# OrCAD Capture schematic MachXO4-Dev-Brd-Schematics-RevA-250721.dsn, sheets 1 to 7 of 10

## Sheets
1 Title page: title: LFMXO4-110-EVN; rev: 1.0; note: 305-PD-25-0689
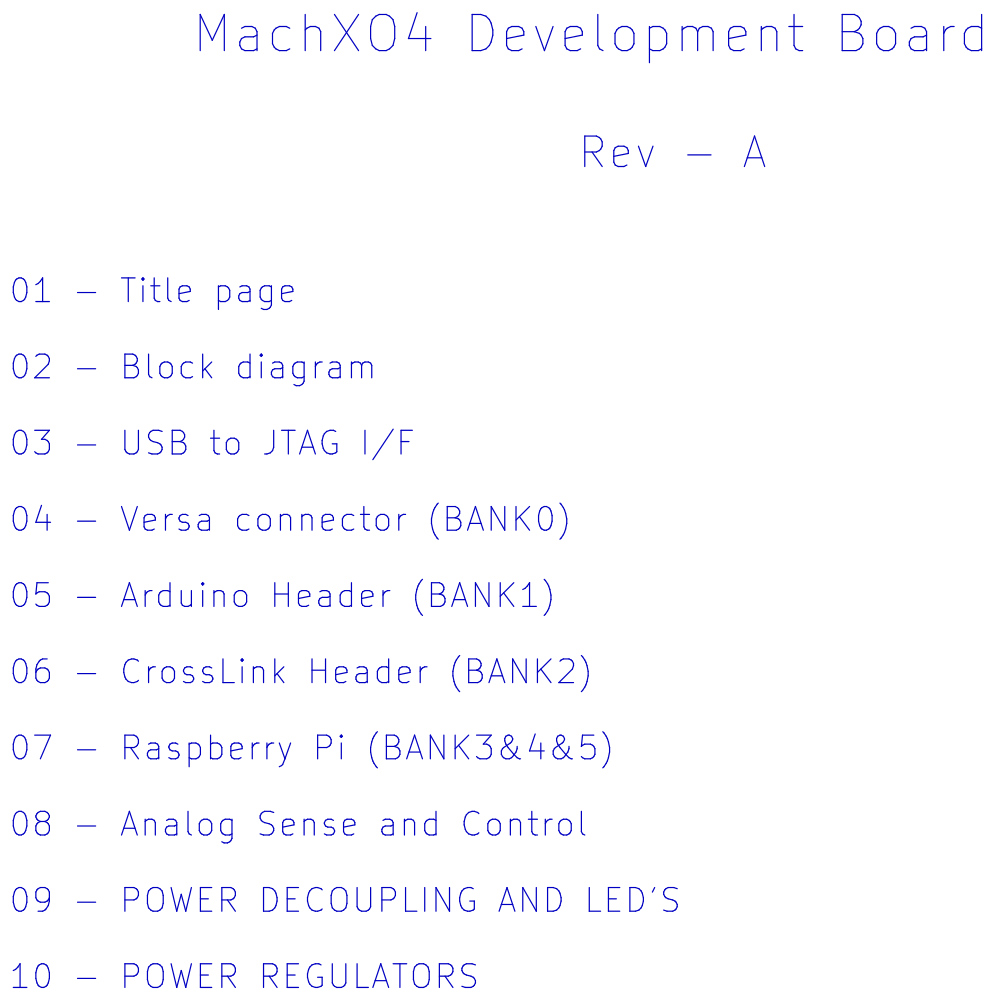
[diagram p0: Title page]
2 Block diagram
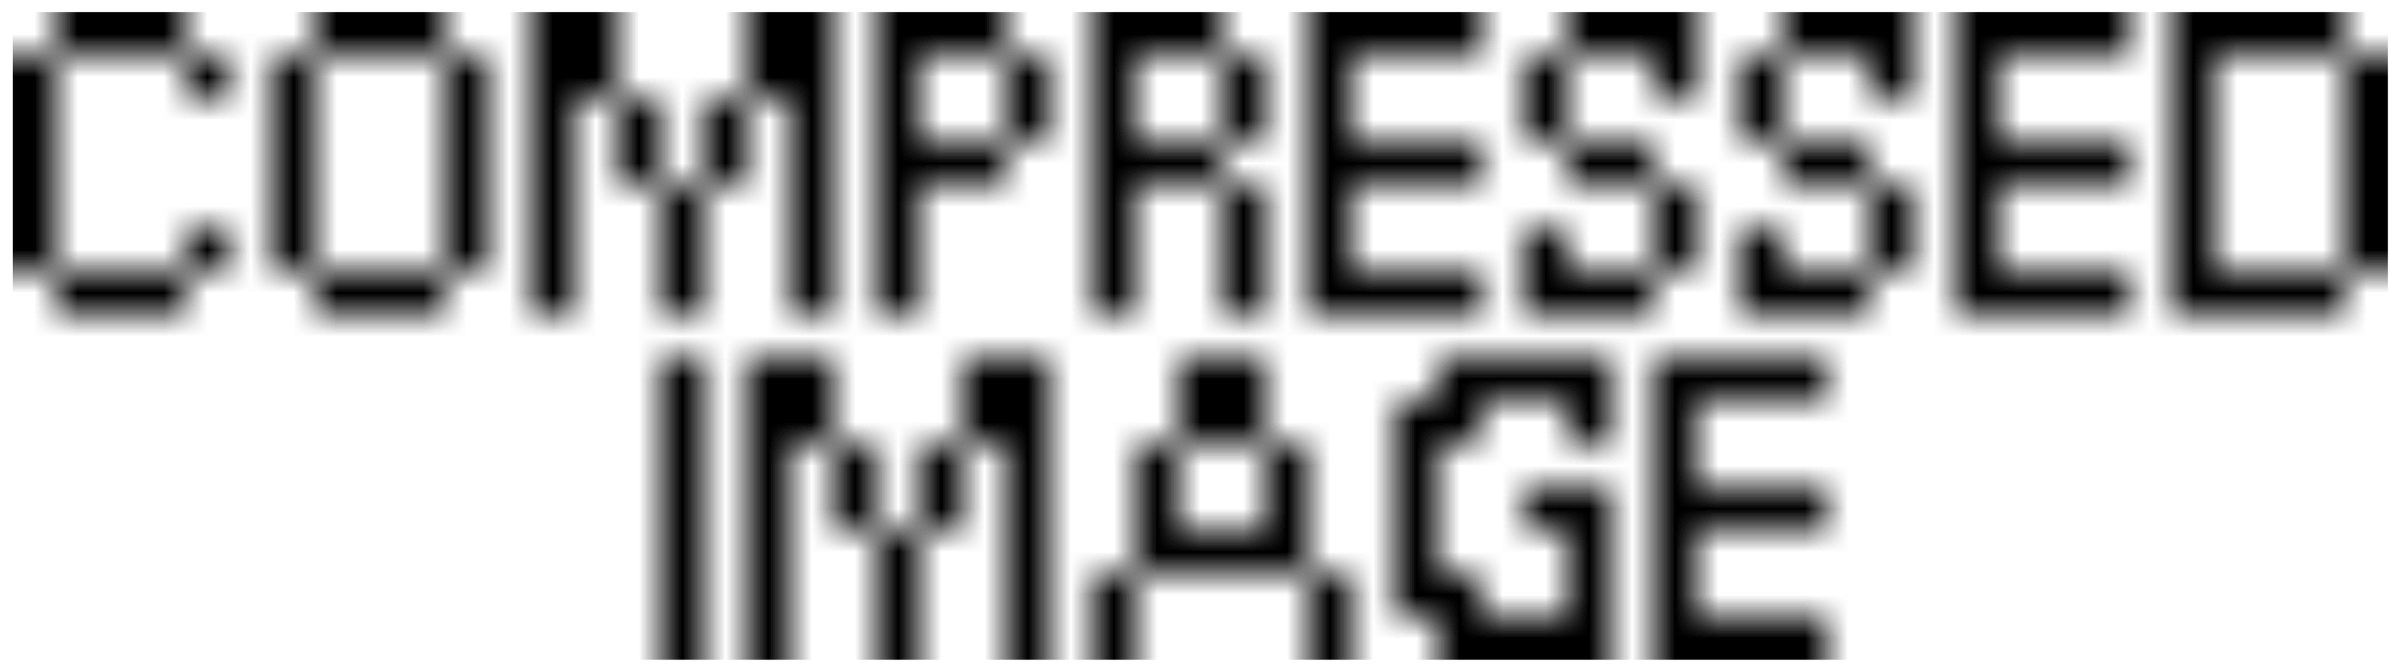
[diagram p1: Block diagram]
3 USB to JTAG I/F: size B
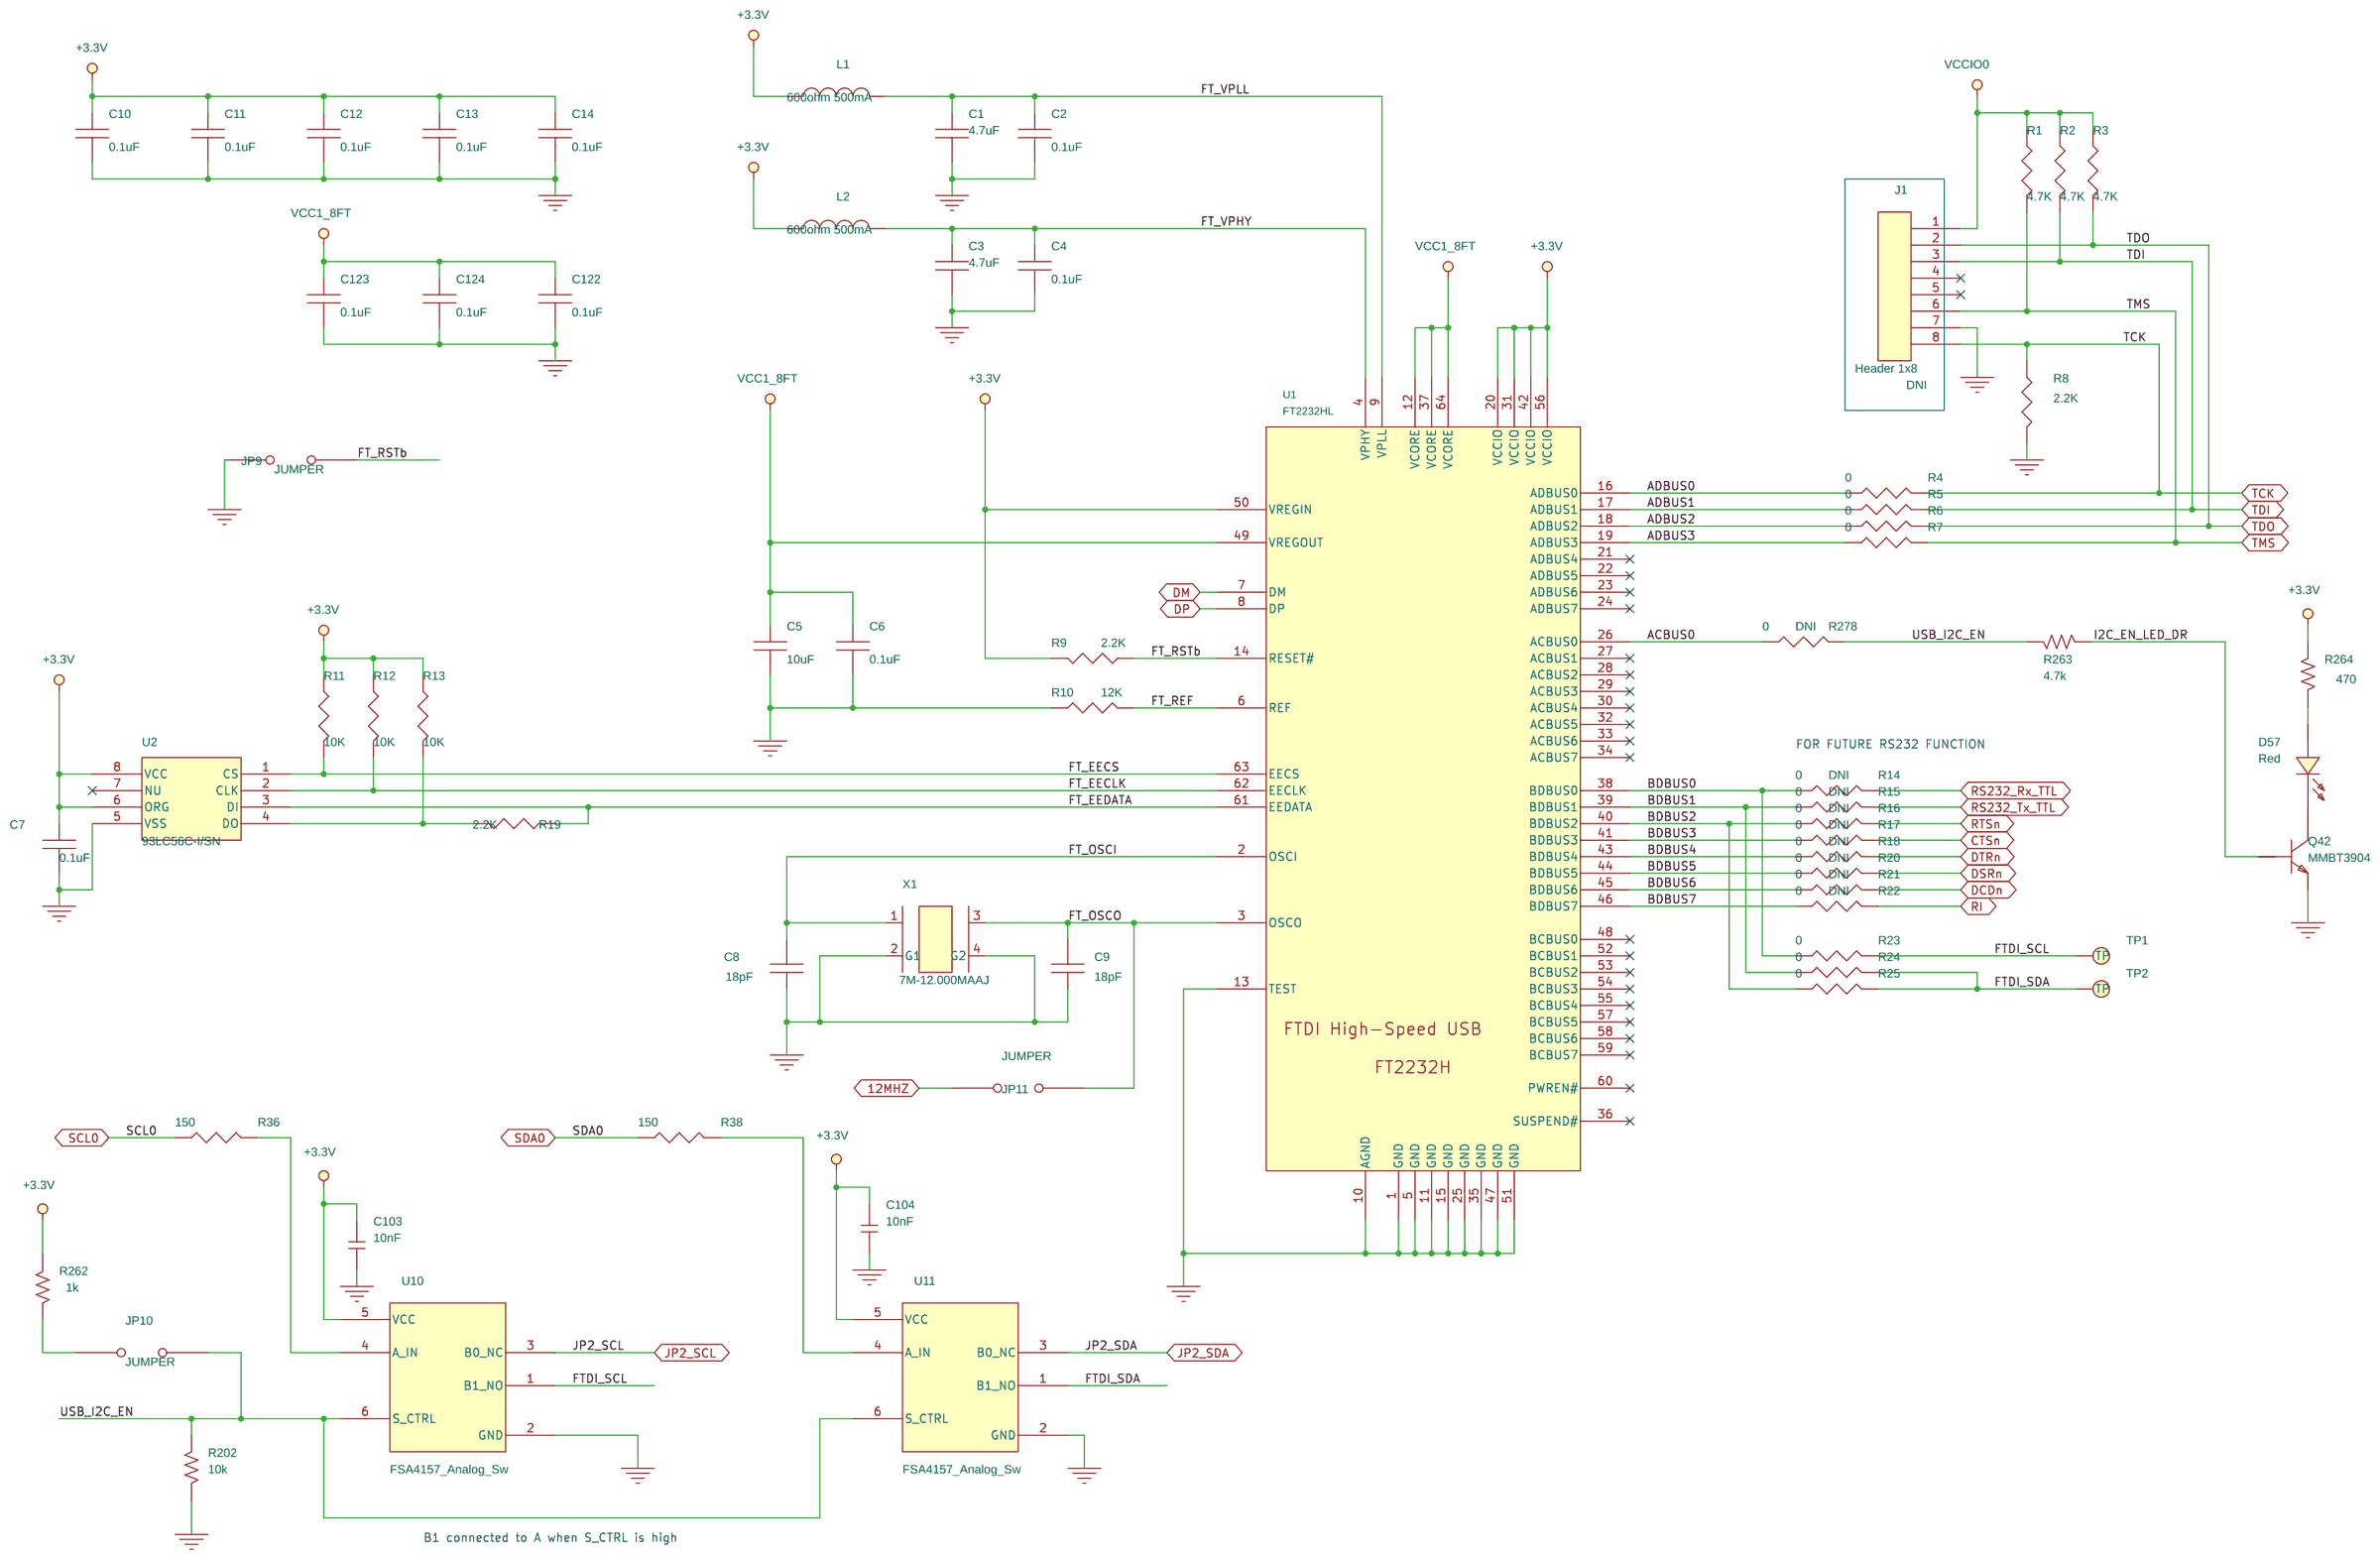
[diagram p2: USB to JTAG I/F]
4 Versa connector (BANK0): size B
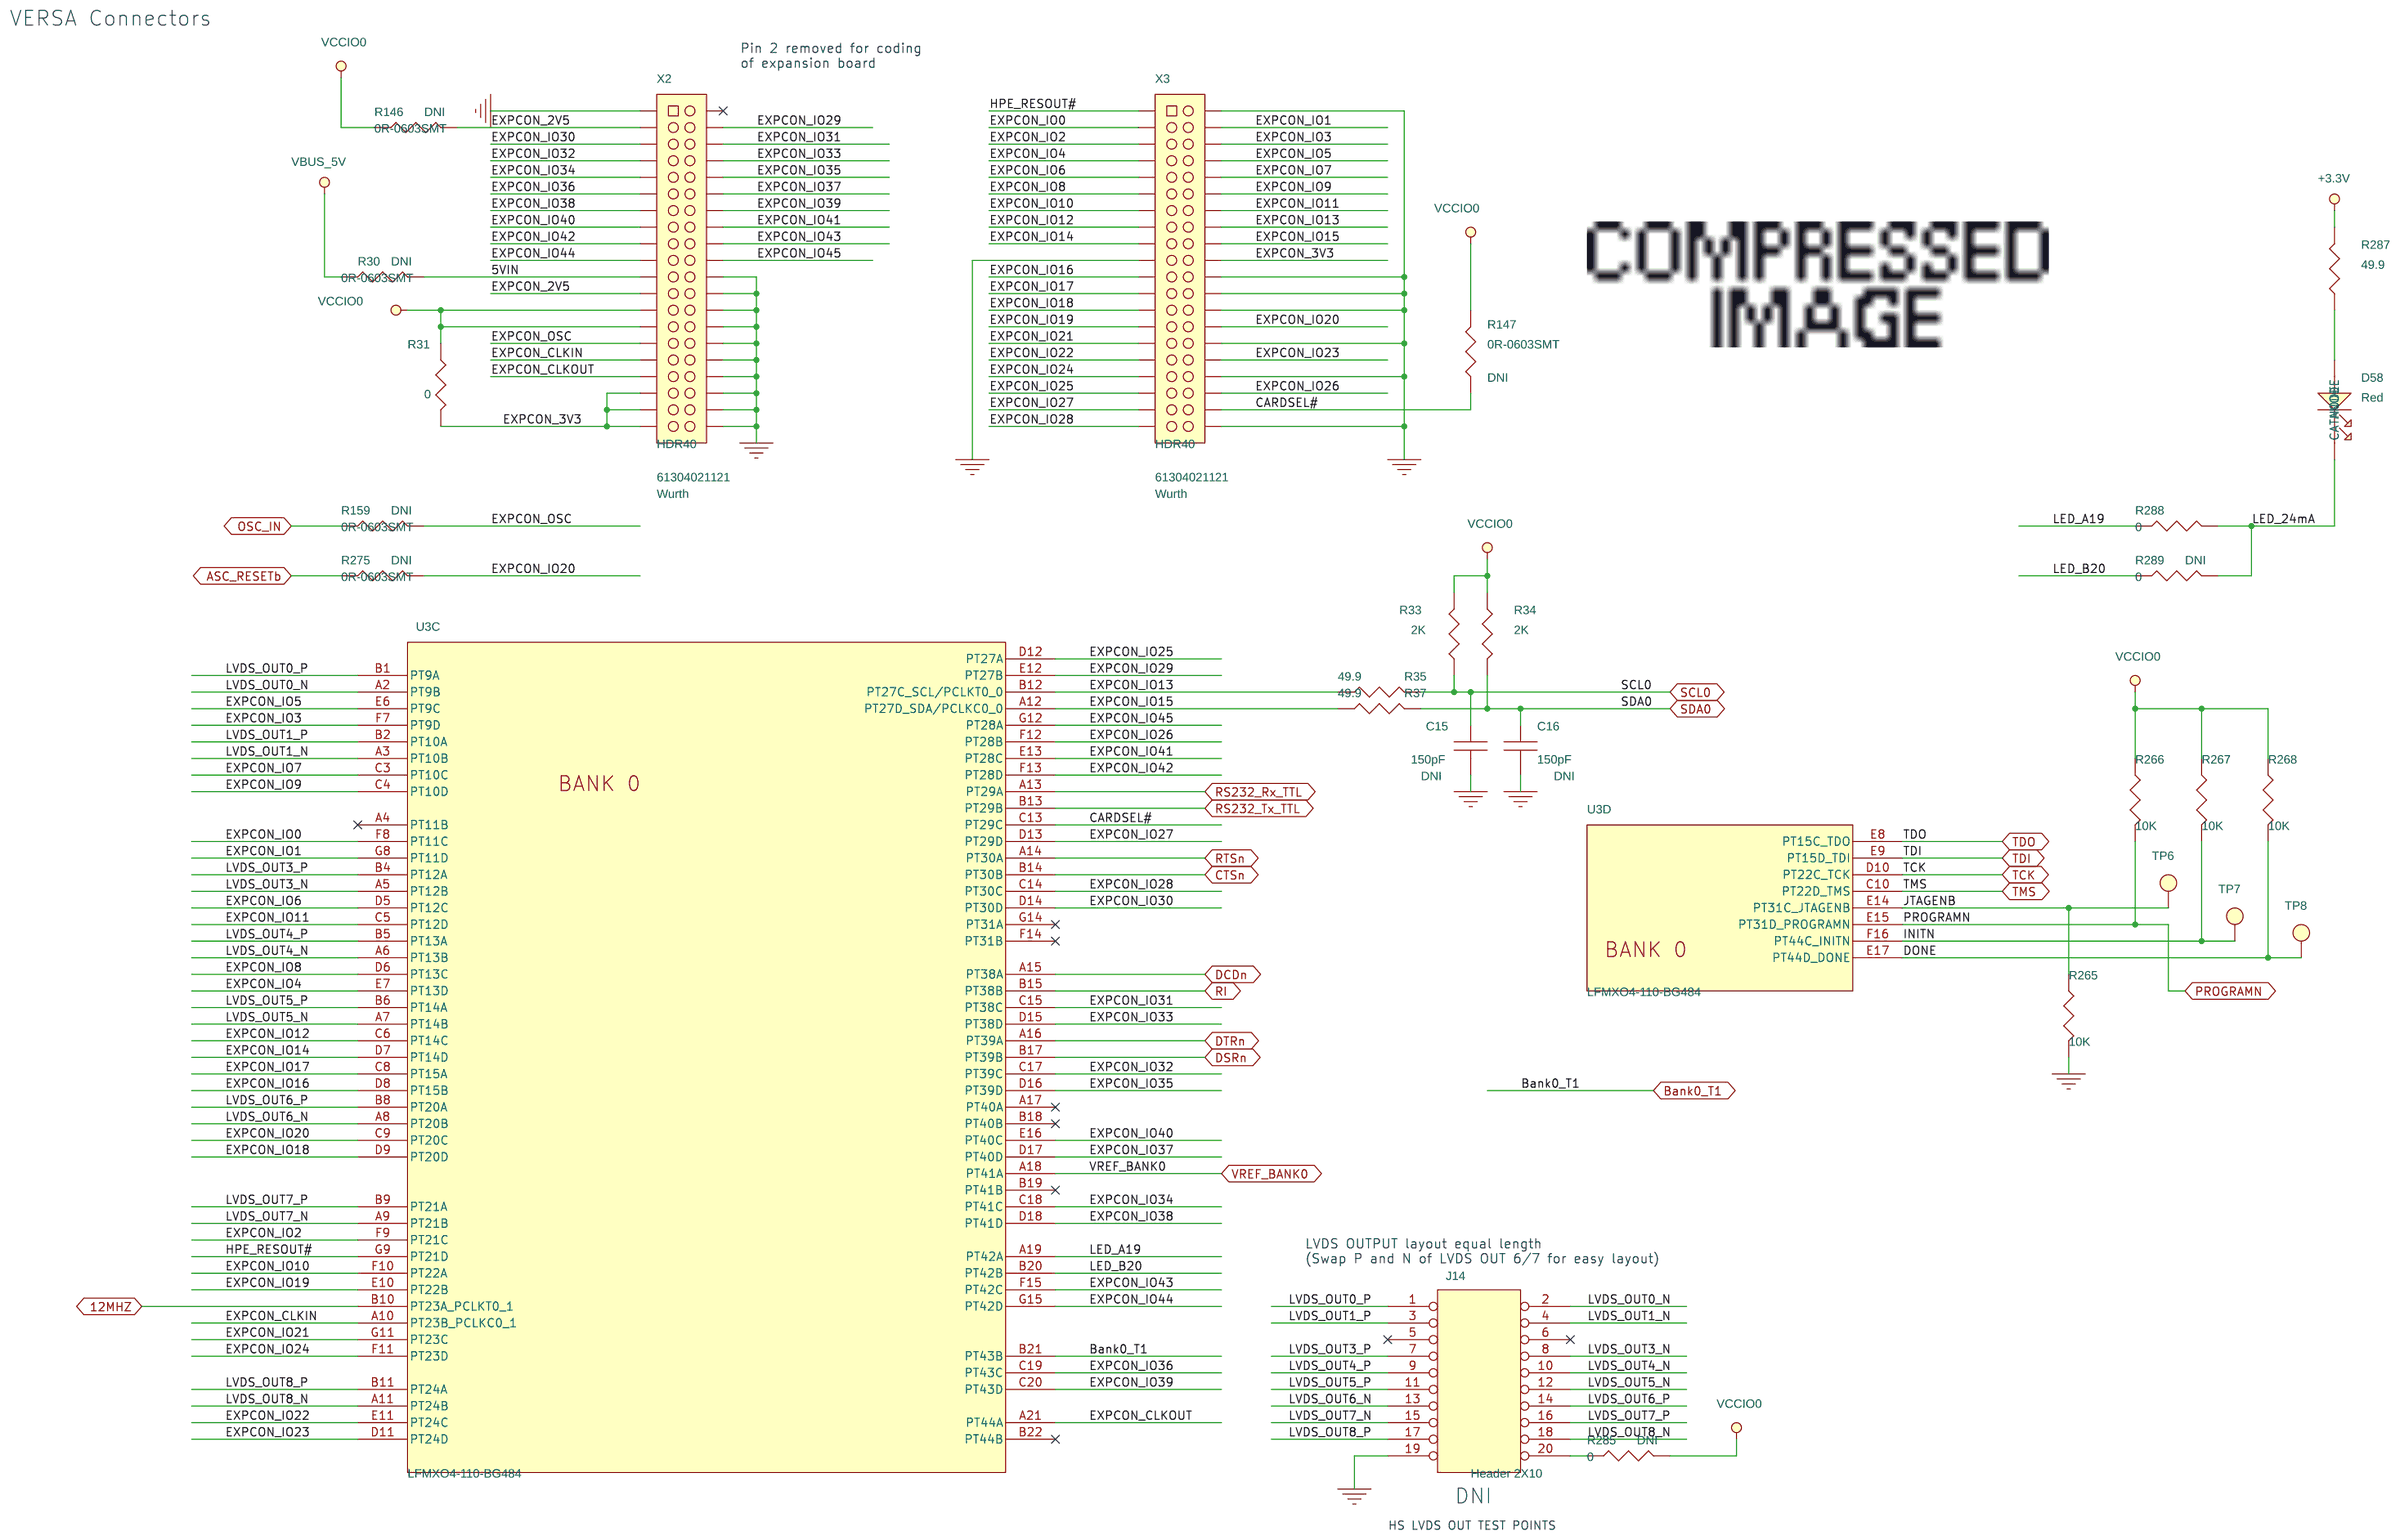
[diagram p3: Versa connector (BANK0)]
5 Arduino Header (BANK1): size B
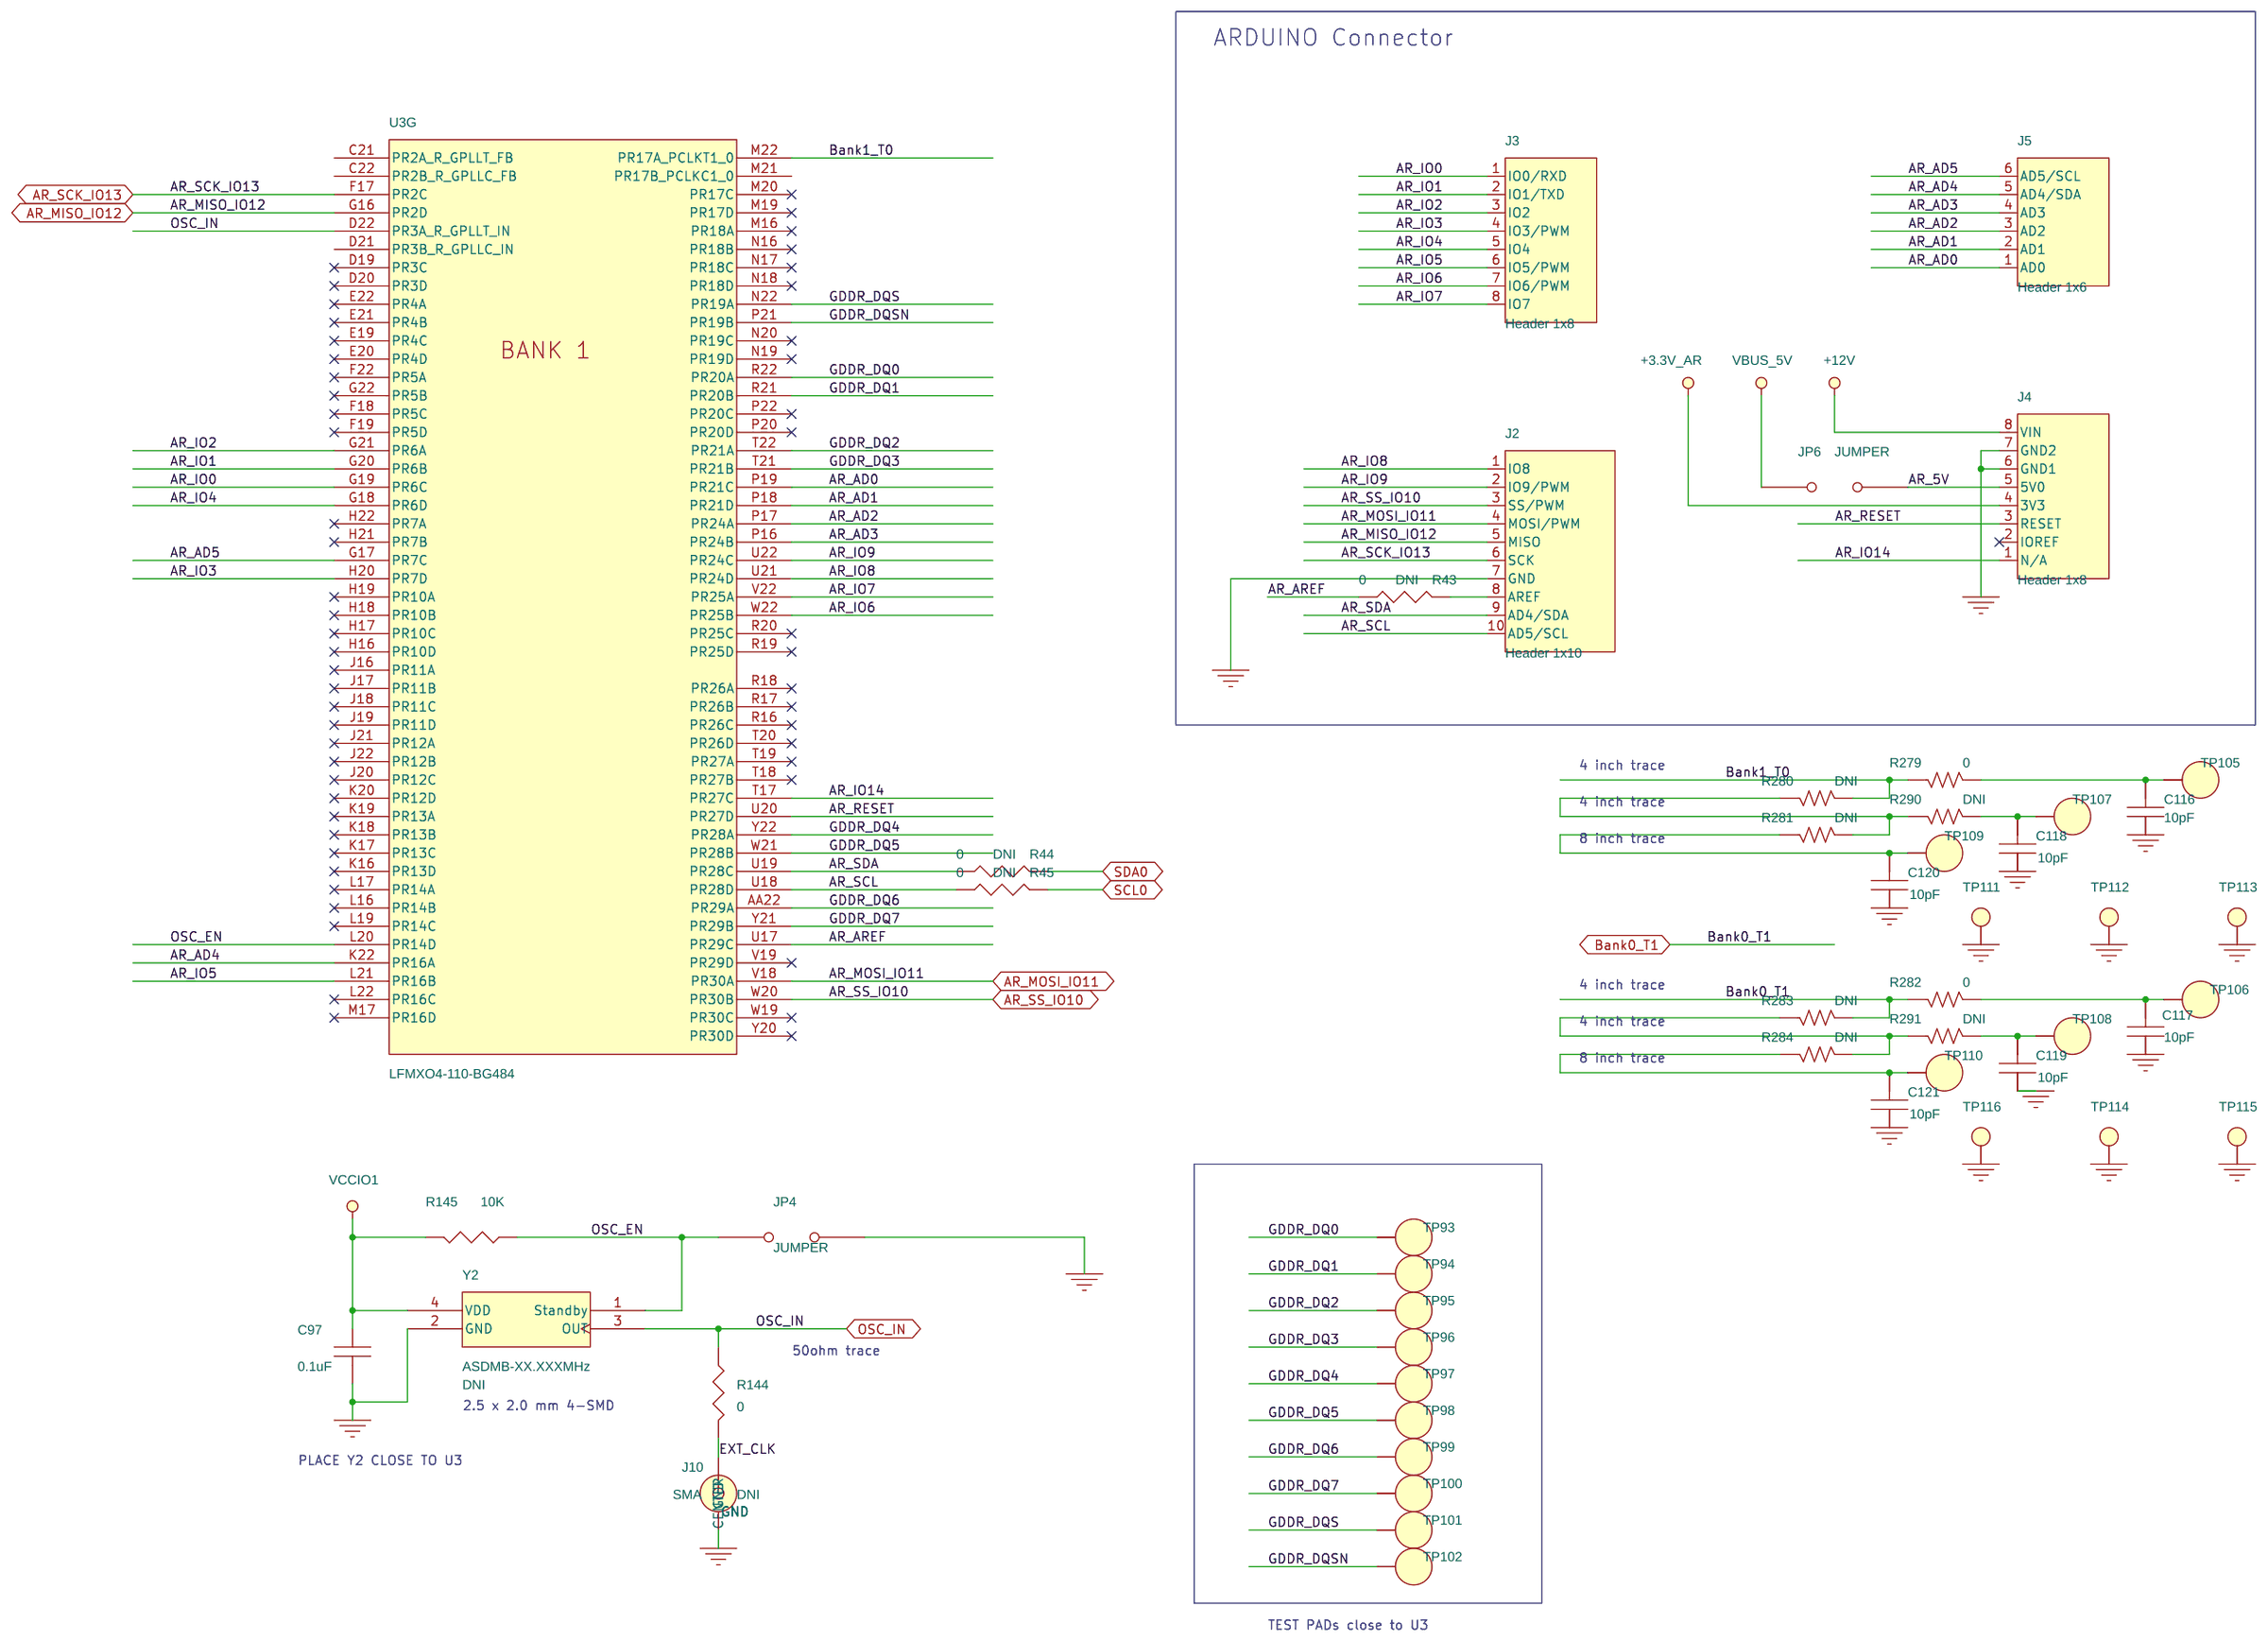
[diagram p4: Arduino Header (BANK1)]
6 CrossLink Header (BANK2): size C
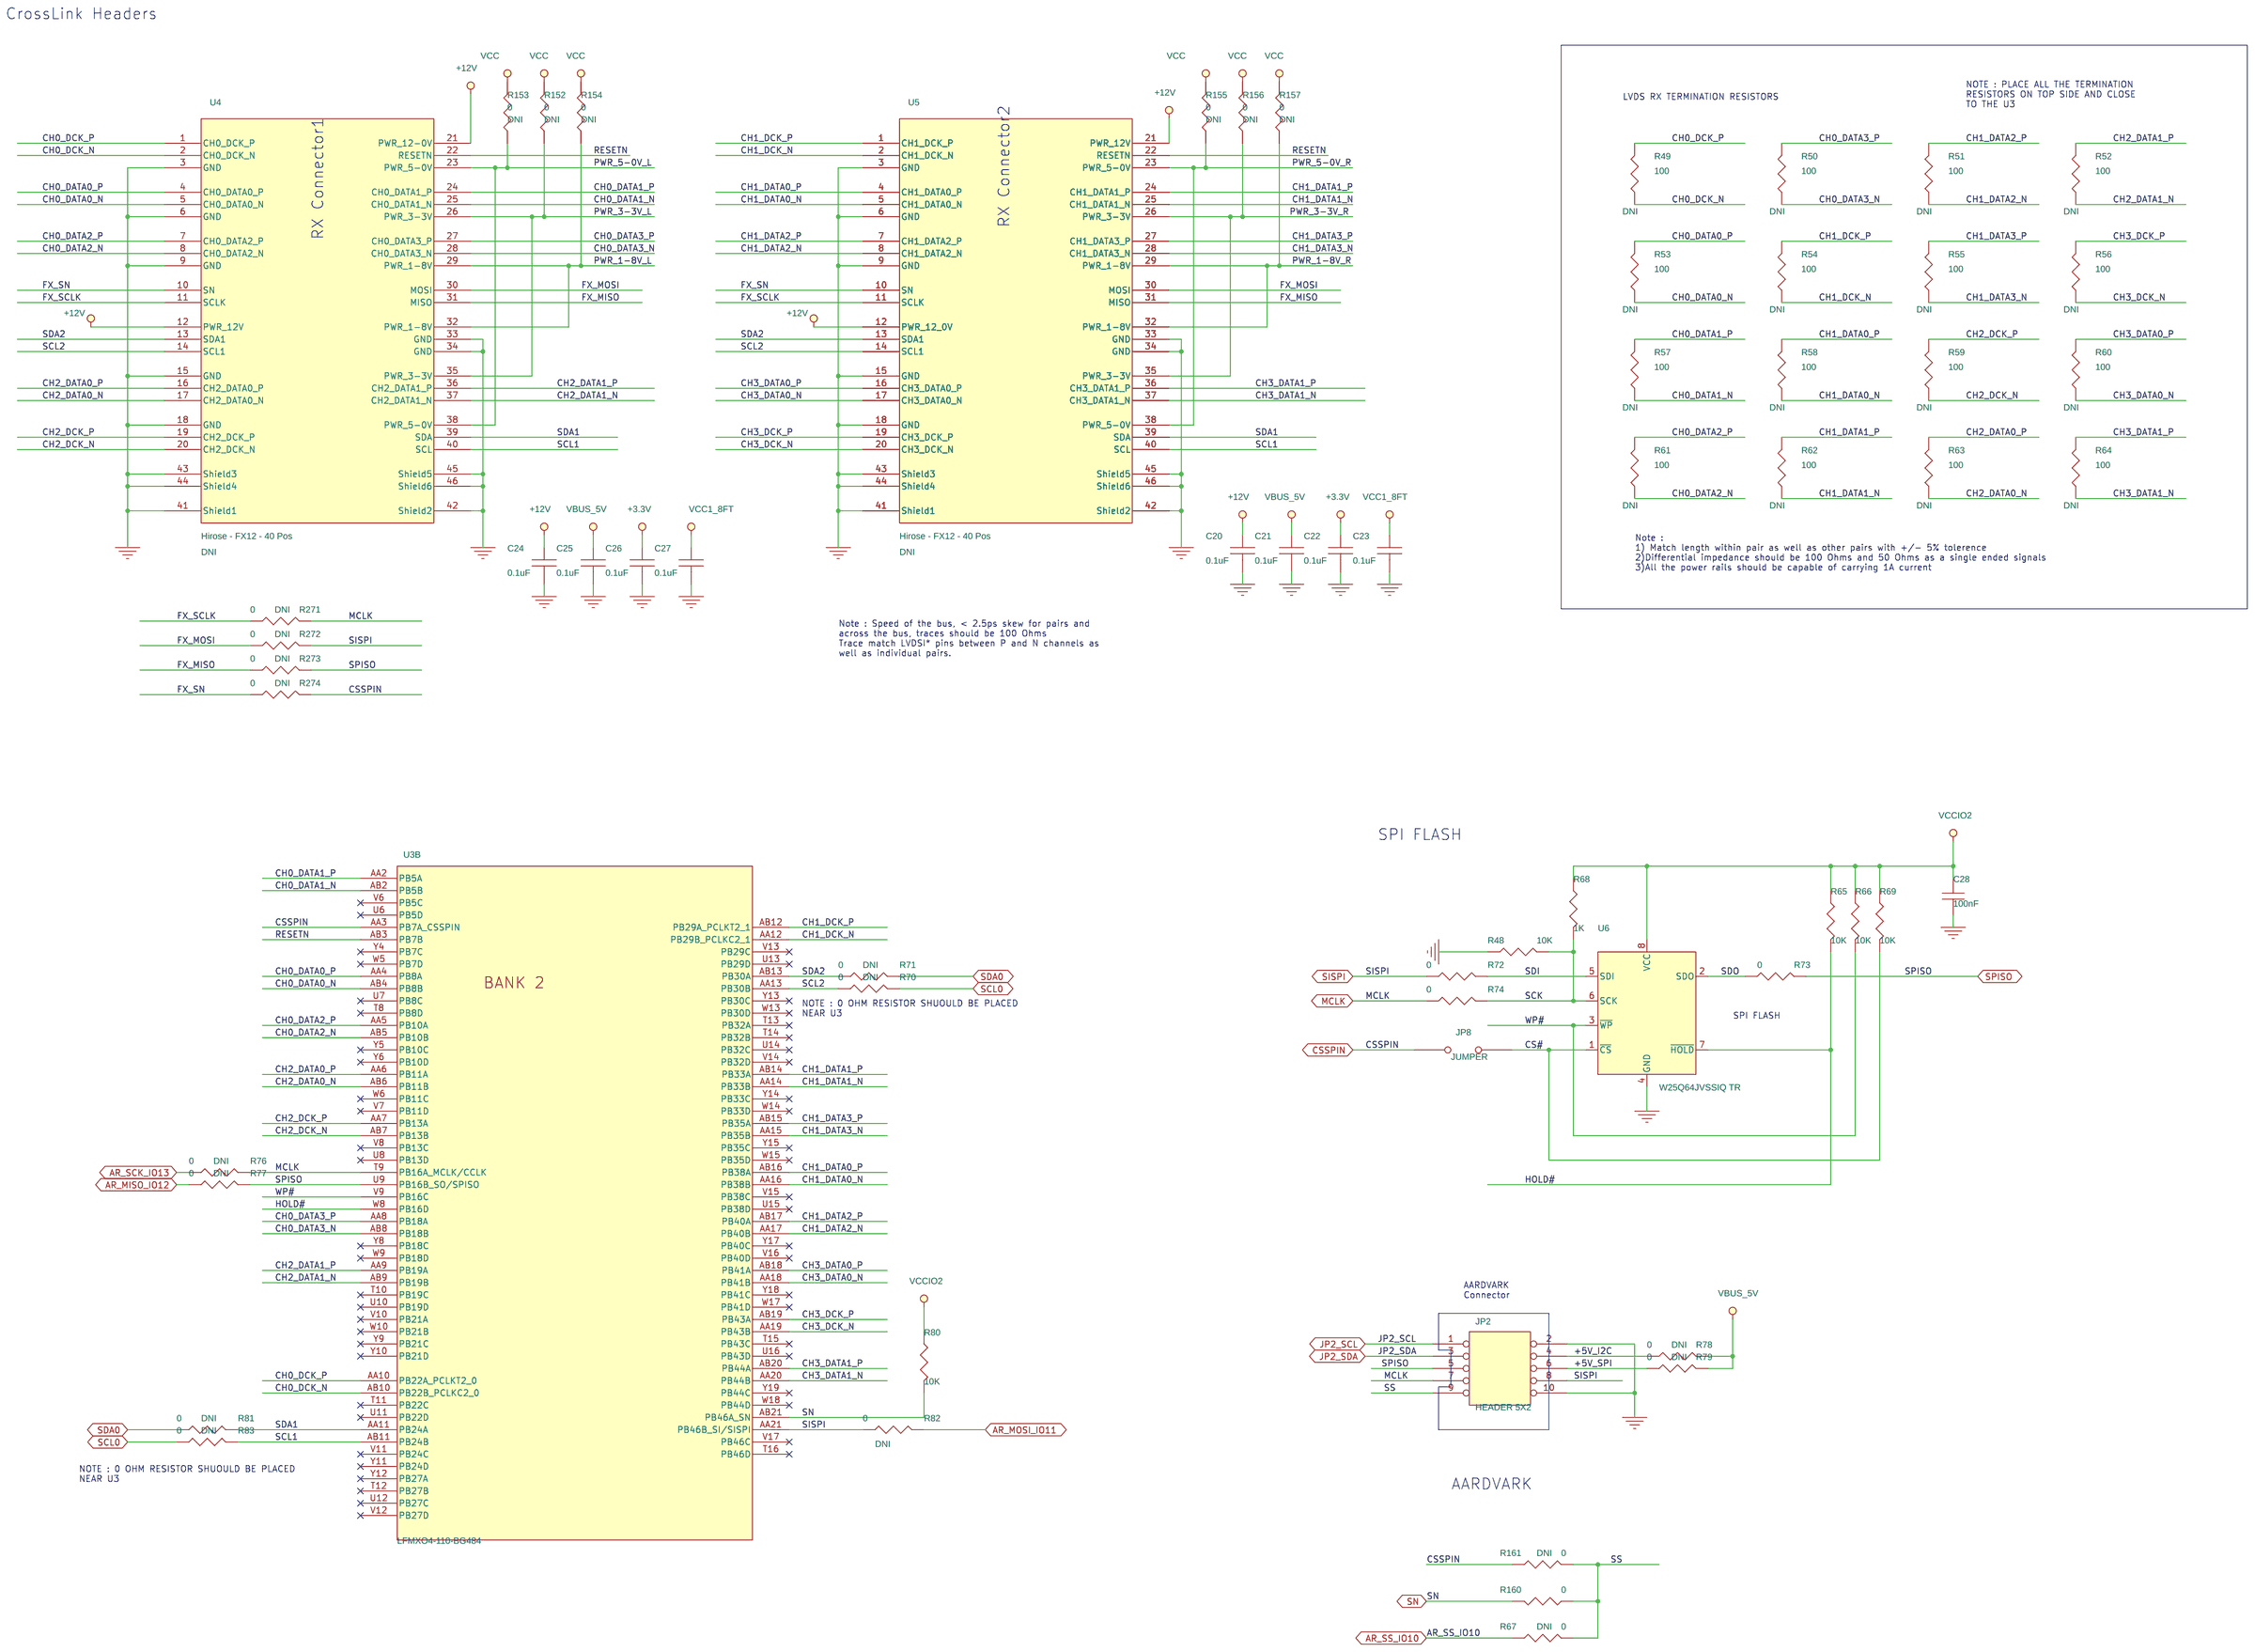
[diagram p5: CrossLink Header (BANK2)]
7 Raspberry Pi (BANK3&4&5): size B
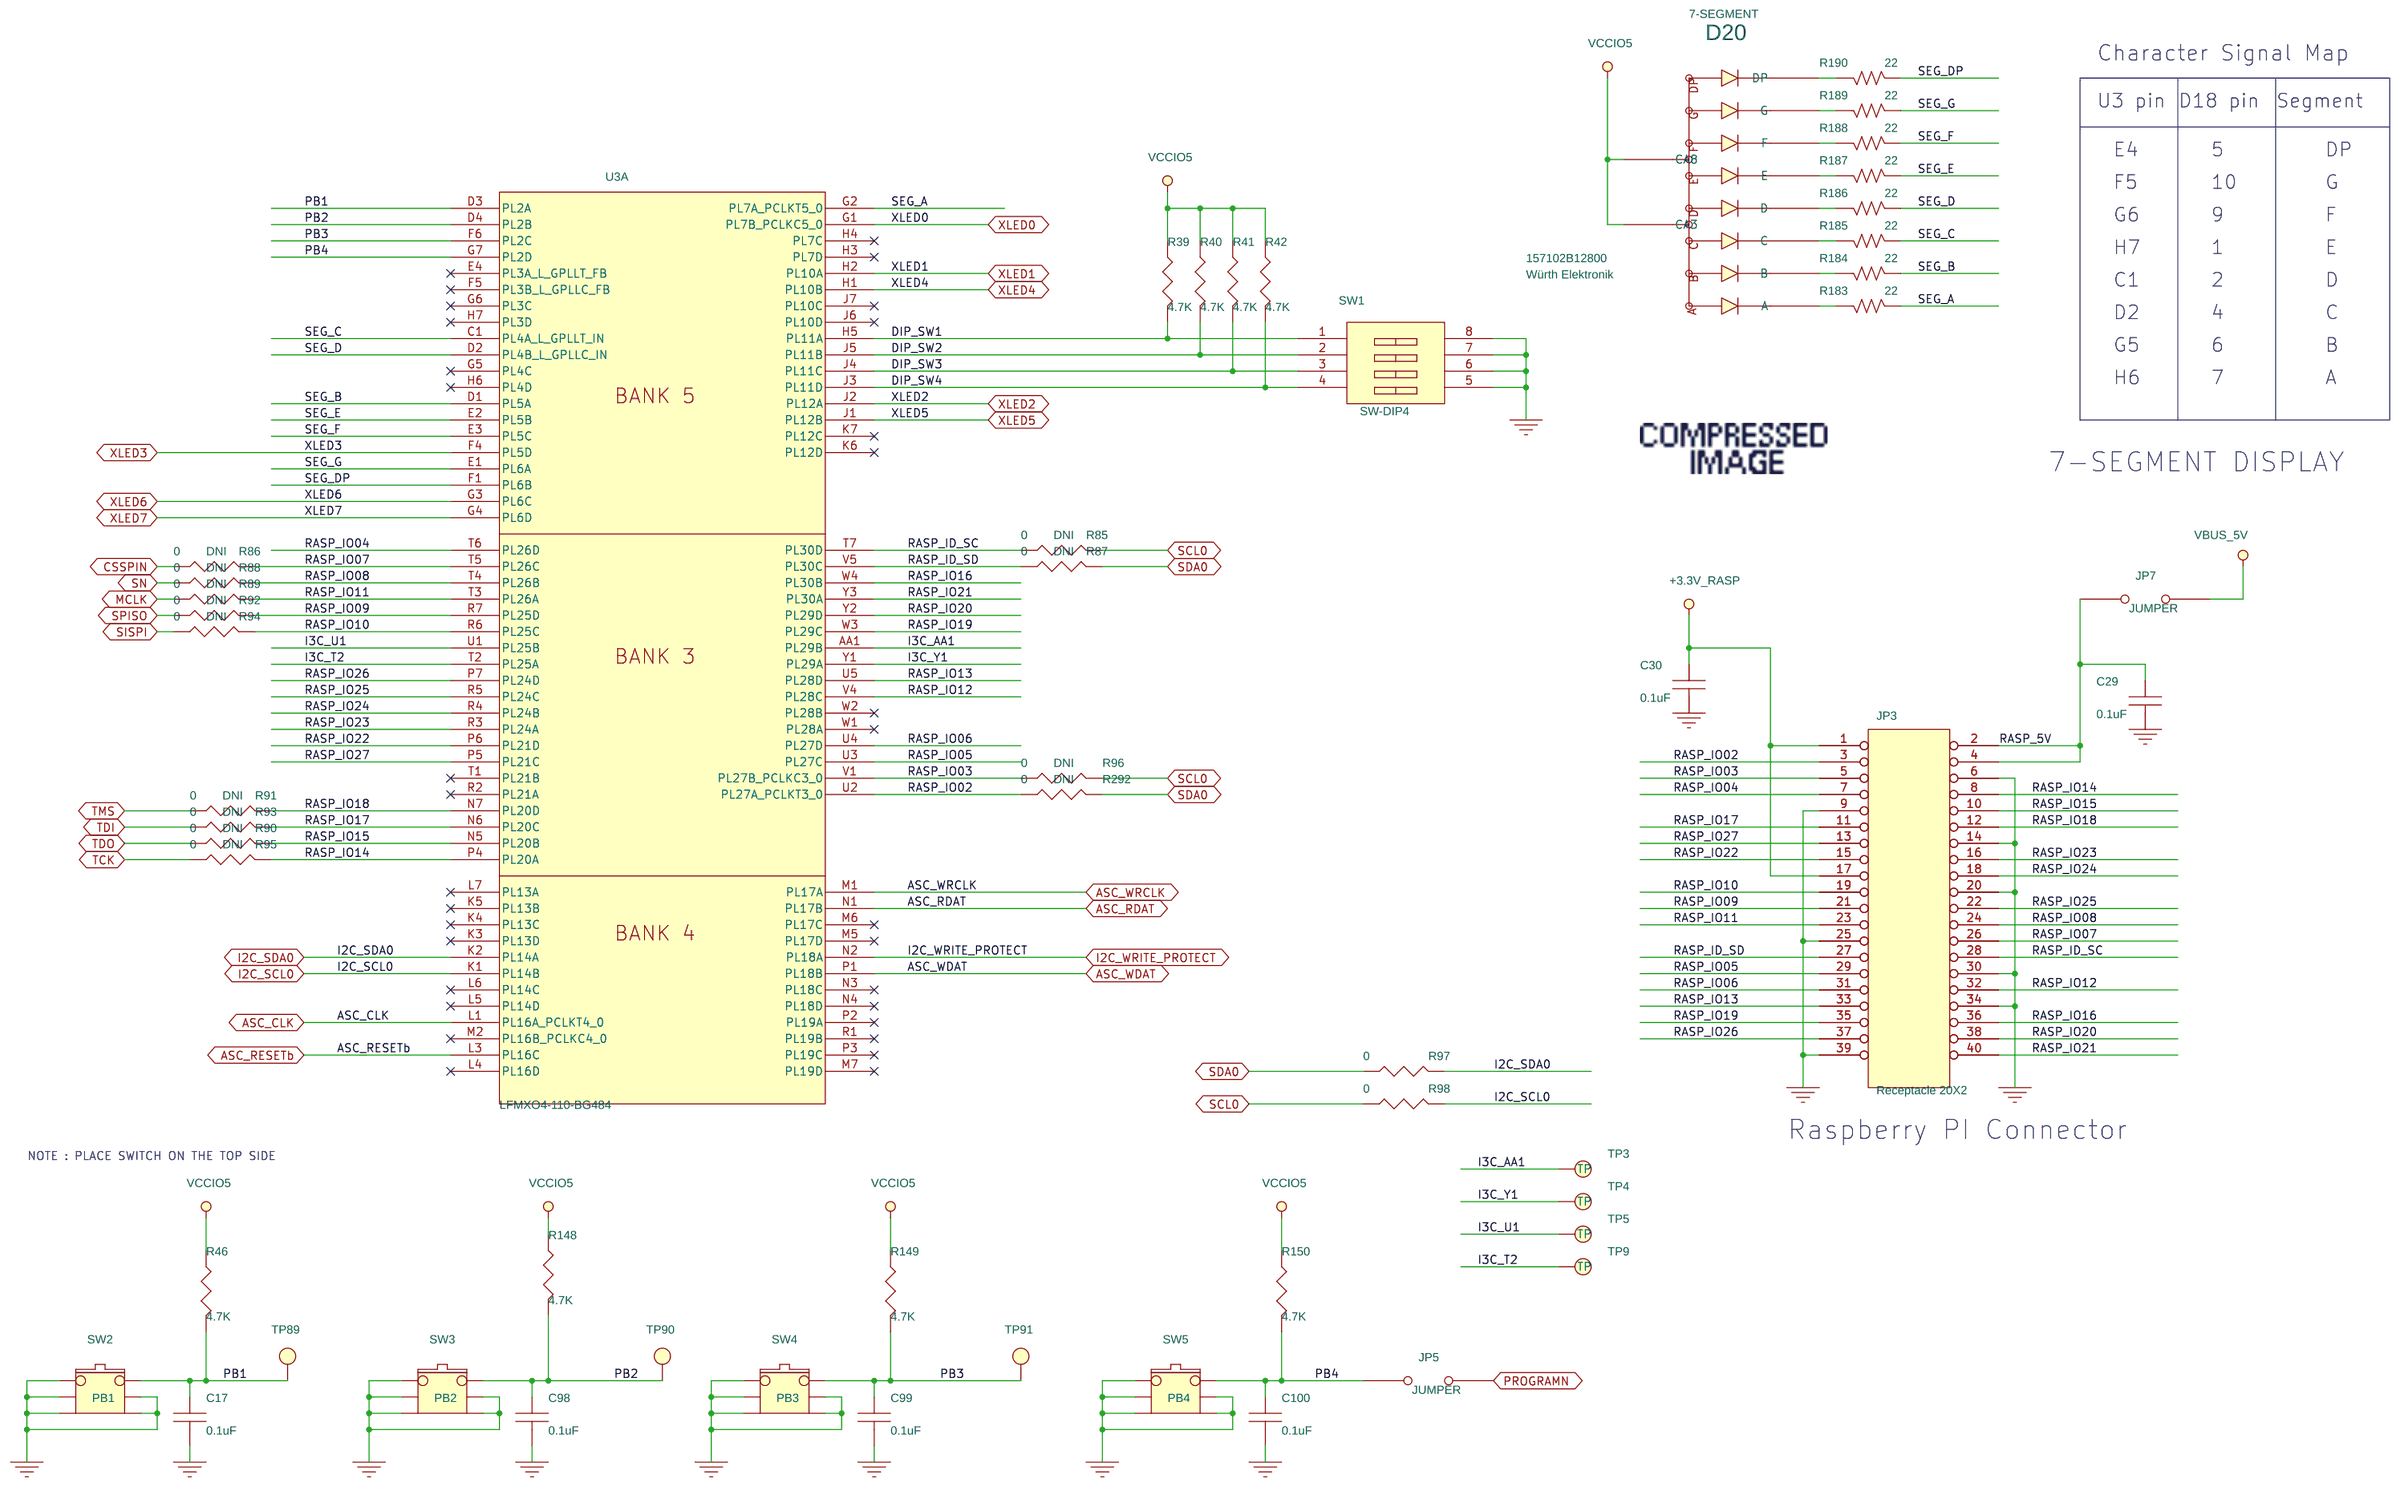
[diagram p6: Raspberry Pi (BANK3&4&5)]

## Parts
sheet Arduino Header (BANK1)
C97  0.1uF  [C0402]
C116  10pF  [C0402]
C117  10pF  [C0402]
C118  10pF  [C0402]
C119  10pF  [C0402]
C120  10pF  [C0402]
C121  10pF  [C0402]
J2  Header 1x10  [CONF1X10-254P_2612X240X850H_TH]
J3  Header 1x8  [CONF1X8-254P_2104X240X850H_TH]
J4  Header 1x8  [CONF1X8-254P_2104X240X850H_TH]
J5  Header 1x6  [CONF1X6-254P_1596X240X850H_TH]
J10  SMA  [bnc5-100-280t]
JP4  JUMPER  [Header_1x2]
JP6  JUMPER  [Header_1x2]
R43  0  [R0603]
R44  0  [R0603]
R45  0  [R0603]
R144  0  [R0402]
R145  10K  [R0603]
R279  0  [R0603]
R280  DNI  [R0603]
R281  DNI  [R0603]
R282  0  [R0603]
R283  DNI  [R0603]
R284  DNI  [R0603]
R290  DNI  [R0603]
R291  DNI  [R0603]
TP93  T POINT R  [TPC32]
TP94  T POINT R  [TPC32]
TP95  T POINT R  [TPC32]
TP96  T POINT R  [TPC32]
TP97  T POINT R  [TPC32]
TP98  T POINT R  [TPC32]
TP99  T POINT R  [TPC32]
TP100  T POINT R  [TPC32]
TP101  T POINT R  [TPC32]
TP102  T POINT R  [TPC32]
TP105  T POINT R  [TPC32]
TP106  T POINT R  [TPC32]
TP107  T POINT R  [TPC32]
TP108  T POINT R  [TPC32]
TP109  T POINT R  [TPC32]
TP110  T POINT R  [TPC32]
TP111  T POINT R  [TPC32]
TP112  T POINT R  [TPC32]
TP113  T POINT R  [TPC32]
TP114  T POINT R  [TPC32]
TP115  T POINT R  [TPC32]
TP116  T POINT R  [TPC32]
Y2  ASDMB-XX.XXXMHz  [x4-2520]
sheet CrossLink Header (BANK2)
C20  0.1uF  [C0402]
C21  0.1uF  [C0402]
C22  0.1uF  [C0402]
C23  0.1uF  [C0402]
C24  0.1uF  [C0402]
C25  0.1uF  [C0402]
C26  0.1uF  [C0402]
C27  0.1uF  [C0402]
C28  100nF  [C0402]
JP2  HEADER 5X2  [HDR254-2X5_SHROUDED]
JP8  JUMPER  [Header_1x2]
R48  10K  [R0603]
R49  100  [R0402]
R50  100  [R0402]
R51  100  [R0402]
R52  100  [R0402]
R53  100  [R0402]
R54  100  [R0402]
R55  100  [R0402]
R56  100  [R0402]
R57  100  [R0402]
R58  100  [R0402]
R59  100  [R0402]
R60  100  [R0402]
R61  100  [R0402]
R62  100  [R0402]
R63  100  [R0402]
R64  100  [R0402]
R65  10K  [R0603]
R66  10K  [R0603]
R67  0  [R0603]
R68  1K  [R0603]
R69  10K  [R0603]
R70  0  [R0603]
R71  0  [R0603]
R72  0  [R0603]
R73  0  [R0603]
R74  0  [R0603]
R76  0  [R0603]
R77  0  [R0603]
R78  0  [R0603]
R79  0  [R0603]
R80  10K  [R0603]
R81  0  [R0603]
R82  0  [R0603]
R83  0  [R0603]
R152  0  [R0603]
R153  0  [R0603]
R154  0  [R0603]
R155  0  [R0603]
R156  0  [R0603]
R157  0  [R0603]
R160  0  [R0603]
R161  0  [R0603]
R271  0  [R0603]
R272  0  [R0603]
R273  0  [R0603]
R274  0  [R0603]
U4  Hirose - FX12 - 40 Pos  [Hirose-FX12]
U5  Hirose - FX12 - 40 Pos  [Hirose-FX12]
U6  W25Q64JVSSIQ TR  [SOIC8_W25Q64JV]
sheet POWER DECOUPLING AND LED'S
U3  LFMXO4-110-BG484  [BGA484-080]  (sections A,B,C,D,E,F,G)
sheet Raspberry Pi (BANK3&4&5)
C17  0.1uF  [C0402]
C29  0.1uF  [C0402]
C30  0.1uF  [C0402]
C98  0.1uF  [C0402]
C99  0.1uF  [C0402]
C100  0.1uF  [C0402]
D20  7-SEGMENT  [LED_157102B12800]
JP3  Receptacle 20X2  [HDR254-2X20_socket]
JP5  JUMPER  [Header_1x2]
JP7  JUMPER  [Header_1x2]
R39  4.7K  [R0603]
R40  4.7K  [R0603]
R41  4.7K  [R0603]
R42  4.7K  [R0603]
R46  4.7K  [R0603]
R85  0  [R0603]
R86  0  [R0603]
R87  0  [R0603]
R88  0  [R0603]
R89  0  [R0603]
R90  0  [R0603]
R91  0  [R0603]
R92  0  [R0603]
R93  0  [R0603]
R94  0  [R0603]
R95  0  [R0603]
R96  0  [R0603]
R97  0  [R0603]
R98  0  [R0603]
R148  4.7K  [R0603]
R149  4.7K  [R0603]
R150  4.7K  [R0603]
R183  22  [R0603]
R184  22  [R0603]
R185  22  [R0603]
R186  22  [R0603]
R187  22  [R0603]
R188  22  [R0603]
R189  22  [R0603]
R190  22  [R0603]
R292  0  [R0603]
SW1  SW-DIP4  [sw_sp_st_cts_195-4mst]
SW2  PB1  [sw_sp_st_eswitch_tl1015]
SW3  PB2  [sw_sp_st_eswitch_tl1015]
SW4  PB3  [sw_sp_st_eswitch_tl1015]
SW5  PB4  [sw_sp_st_eswitch_tl1015]
TP3  TP_S_40_63  [TP]
TP4  TP_S_40_63  [TP]
TP5  TP_S_40_63  [TP]
TP9  TP_S_40_63  [TP]
TP89  TestPoint  [TP]
TP90  TestPoint  [TP]
TP91  TestPoint  [TP]
sheet USB to JTAG I/F
C1  4.7uF  [C0603]
C2  0.1uF  [C0402]
C3  4.7uF  [C0603]
C4  0.1uF  [C0402]
C5  10uF  [C0603]
C6  0.1uF  [C0402]
C7  0.1uF  [C0402]
C8  18pF  [C0402]
C9  18pF  [C0402]
C10  0.1uF  [C0402]
C11  0.1uF  [C0402]
C12  0.1uF  [C0402]
C13  0.1uF  [C0402]
C14  0.1uF  [C0402]
C103  10nF  [SM_C_0603]
C104  10nF  [SM_C_0603]
C122  0.1uF  [C0402]
C123  0.1uF  [C0402]
C124  0.1uF  [C0402]
D57  Red  [led_0603]
J1  Header 1x8  [hdr_amp_87220_8_1x8_100]
JP9  JUMPER  [Header_1x2]
JP10  JUMPER  [Header_1x2]
JP11  JUMPER  [Header_1x2]
L1  600ohm 500mA  [fb0603]
L2  600ohm 500mA  [fb0603]
Q42  MMBT3904  [MMBT3904]
R1  4.7K  [R0603]
R2  4.7K  [R0603]
R3  4.7K  [R0603]
R4  0  [R0603]
R5  0  [R0603]
R6  0  [R0603]
R7  0  [R0603]
R8  2.2K  [R0603]
R9  2.2K  [R0603]
R10  12K  [R0603]
R11  10K  [R0603]
R12  10K  [R0603]
R13  10K  [R0603]
R14  0  [R0603]
R15  0  [R0603]
R16  0  [R0603]
R17  0  [R0603]
R18  0  [R0603]
R19  2.2K  [R0603]
R20  0  [R0603]
R21  0  [R0603]
R22  0  [R0603]
R23  0  [R0603]
R24  0  [R0603]
R25  0  [R0603]
R36  150  [R0603]
R38  150  [R0603]
R202  10k  [R0603]
R262  1k  [R0603]
R263  4.7k  [R0603]
R264  470  [R0603]
R278  0  [R0603]
TP1  TP_S_40_63  [TP]
TP2  TP_S_40_63  [TP]
U1  FT2232HL  [tqfp64_0p5_12p2x12p2_h1p6]
U2  93LC56C-I/SN  [so8_50_244]
U10  FSA4157_Analog_Sw  [SOP-6-26]
U11  FSA4157_Analog_Sw  [SOP-6-26]
X1  7M-12.000MAAJ  [xtal_4p_7m]
sheet Versa connector (BANK0)
C15  150pF  [C0402]
C16  150pF  [C0402]
D58  Red  [led_0603]
J14  Header 2X10  [HDR100-10X2]
R30  0R-0603SMT  [R0603]
R31  0  [R0603]
R33  2K  [R0603]
R34  2K  [R0603]
R35  49.9  [R0603]
R37  49.9  [R0603]
R146  0R-0603SMT  [R0603]
R147  0R-0603SMT  [R0603]
R159  0R-0603SMT  [R0603]
R265  10K  [R0603]
R266  10K  [R0603]
R267  10K  [R0603]
R268  10K  [R0603]
R275  0R-0603SMT  [R0603]
R285  0  [R0603]
R287  49.9  [R0603]
R288  0  [R0603]
R289  0  [R0603]
TP6  TestPoint  [TP]
TP7  TestPoint  [TP]
TP8  TestPoint  [TP]
X2  HDR40  [HDR-20x2]
X3  HDR40  [HDR-20x2]

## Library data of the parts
C2 C4 C6 C7 C10-C14 C17 C97-C100 C122-C124 = 0u1_0402: CAP CER 0.1UF 16V 10% X7R 0402
C8 C9 C116-C121 = 0u1_0402: CAP CER 18PF 25V 10% NP0 0402; Digikey P/N: C0402C180K3GACTU-ND; Manufacturer Part Number: C0402C180K3GACTU
J2 = 10_PIN_SOCKET_2: Digikey Partnumber: MOUSER_538-90147-1110; IPN: G79666-001
J3 = 8_PIN_SOCKET_0: Digikey Partnumber: MOUSER_538-90147-1108; IPN: H76806-001
J4 = 8_PIN_SOCKET: Digikey Partnumber: MOUSER_538-90147-1108; IPN: H76806-001
J5 = 8_PIN_SOCKET_3: Digikey Partnumber: MOUSER_538-90147-1106; IPN: H98107-001; Intel_B1 PN------: H98107-001
J10 = SMA_0_0.5: Assy: DNI
JP4-JP11 = JUMPER_0
R43-R45 R67 R70 R71 R76-R79 R81-R83 R152-R157 R161 R271-R274 = 0R_0603: Assy: DNI
R144 = R_3
R145 = RESISTOR: RES 10K OHM 1/10W 5% 0603
R279 R282 = R: COMPFIXED: NO; COMPHEIGHT: 0.000; COMPKEY: NO; COMPLOC: [950.000,2200.000]; COMPLOCKED: NO; COMPSIDE: BOT; DECOUPLER: NO; MEMORY: NO; Populate: DI
R183-R190 R280 R281 R283 R284 R290 R291 = R: COMPFIXED: NO; COMPGROUP: 0; COMPHEIGHT: 0.000; COMPKEY: NO; COMPLOC: [950.000,2200.000]; COMPLOCKED: NO; COMPROT: 0; COMPSIDE: BOT; DECOUPLER: NO; MEMORY: NO; Populate: DI
TP93-TP102 TP105-TP110 = T_POINT_R_0: COMPFIXED: NO; COMPGROUP: 0; COMPHEIGHT: 0.000; COMPKEY: NO; COMPLOC: [200.000,3200.000]; COMPLOCKED: NO; COMPROT: 0; COMPSIDE: TOP; DECOUPLER: NO; MEMORY: NO
TP111-TP116 = T_POINT_R_0_v2: COMPFIXED: NO; COMPGROUP: 0; COMPHEIGHT: 0.000; COMPKEY: NO; COMPLOC: [200.000,3200.000]; COMPLOCKED: NO; COMPROT: 0; COMPSIDE: TOP; DECOUPLER: NO; MEMORY: NO
Y2 = ASDMB: Assy: DNI
C20-C27 C29 C30 = 0u1_0402: CAP CER 0.1UF 25V 10% X7R 0402; Manufacturer: AVX; Manufacturer Part Number: 04023C104KAT2A
C28 = CAP_CER_100nF_0402_10V: CAP CER 0.1UF 10V 10% X5R 0402; Digikey P/N: 490-1318-2-ND; Manufacturer: Murata; Manufacturer Part Number: GRM155R61A104KA01D
JP2 = HEADER_5X2_0: CONN HEADER VERT 10POS 2.54MM; MFG: Molex; MFG P/N: 70246-1003; Manufacturer: Molex; Manufacturer Part Number: 70246-1003
R48 R68 = RES_10K_1W16_0402_5P: RES 1K OHM 1/10W 1% 0603 SMD; Digikey P/N: 311-1.00KHRCT-ND; MFG P/N: RC0603FR-071KL; Manufacturer: Yageo; Manufacturer Part Number: RC0603FR-071KL
R49-R64 = 100R_0603: RES SMD 100 OHM 1% 1/16W 0402; Assy: DNI; BOM NOTE: DNI; Manufacturer Part Number: RC0402FR07100RL
R11-R13 R65 R66 R69 R80 R265-R268 = RES_10K_1W16_0402_5P: RES 10K OHM 1/10W 5% 0603; Digikey P/N: RMCF0603JT10K0TR-ND; Manufacturer: Stackpole Electronics Inc; Manufacturer Part Number: RMCF0603JT10K0; Wattage: 1/10W
R4-R7 R23-R25 R72-R74 = 0R_0603: RES 0.0 OHM 1/10W JUMP 0603 SMD
R97 R98 R160 = 0R_0603
U4 = FX12Conn_28: Conn Board to Board PL 40 POS 0.4mm Solder ST SMD T/R; Assy: DNI; Manufacturer: Hirose Electric Co Ltd; Manufacturer Part Number: FX12B-40P-0.4SV
U5 = FX12Conn_27: Conn Board to Board PL 40 POS 0.4mm Solder ST SMD T/R; Assy: DNI; Manufacturer: Hirose Electric Co Ltd; Manufacturer Part Number: FX12B-40P-0.4SV
U6 = SPI_FLASH_32Mb_SOIC8: IC FLASH 64MBIT SPI/QUAD 8SOIC; Digikey P/N: 1274-1088-ND; MFG: Winbond Electronics; Manufacturer: Winbond Electronics
U3 = LFMXO4-110-BG484
D20 = LTP-587_2: WL-S7DS 7 SEGMENTS DISPLAY SMT S; Manufacturer: Würth Elektronik; Manufacturer Part Number: 157102B12800
JP3 = Receptacle_20X2
R1-R3 R39-R42 R46 R148-R150 = 5k1_0402: RES 4.70K OHM 1/10W 1% 0603 SMD; Digikey P/N: 541-4.70KHTR-ND; Manufacturer: Vishay; Manufacturer Part Number: CRCW06034K70FKEA
R14-R18 R20-R22 R85-R96 R278 R292 = 0R_0603: RES 0.0 OHM 1/10W JUMP 0603 SMD; Assy: DNI
SW1 = DIP-SW: SWITCH SIDE ACTUATED 4 SEC 50V; Digikey P/N: CT1954MST-ND; Manufacturer: CTS Electrocomponents; Manufacturer Part Number: 195-4MST
SW2-SW5 = SW_PUSHBUTTON-SPST_SM_0: SWITCH TACTILE SPST-NO 0.05A 12V; Digikey P/N: EG4344TR-ND; MFG: E-Switch Inc; MFG P/N: TL1015AF160QG; Man. Part #: TL1015AF160QG; Manufacturer: E-Switch; Manufacturer Part Number: TL1015AF160QG
TP1-TP5 TP9 = TP_S_40_63: Assy: DNI
TP89-TP91 = T_POINT_R: Assy: DNI
C1 C3 = 4u7_0603: CAP CER 4.7UF 6.3V 10% X5R 0603; Digikey P/N: PCC2396CT-ND
C5 = 10uF_0603: CAP CER 10UF 10V 20% X5R 0603
C103 C104 = C: COMPFIXED: NO; COMPGROUP: 0; COMPHEIGHT: 0.000; COMPKEY: NO; COMPLOC: [3445.000,1400.000]; COMPLOCKED: NO; COMPROT: 180; COMPSIDE: TOP; DECOUPLER: NO; FPLIST: RAD/CK05; MEMORY: NO; Populate: DI
D57 = LED: COMPFIXED: NO; COMPGROUP: 0; COMPHEIGHT: 0.000; COMPKEY: NO; COMPLOCKED: NO; COMPROT: 0; COMPSIDE: TOP; DECOUPLER: NO; MEMORY: NO; Populate: DI
J1 = header1x8_100: CONN HEADER 8POS .100 VERT TIN; Assy: DNI; Digikey P/N: WM50017-08-ND; Manufacturer Part Number: 0022284081
L1 L2 = FB0603: FERRITE CHIP 600 OHM 500MA 0603
Q42 = 2N3904_1
R8 R9 = 5k1_0402: RES 2.2K OHM 1% 1/10W 0603; Digikey P/N: 541-2.20KHTR-ND; Manufacturer: Yageo; Manufacturer Part Number: RC0603FR-072K2L; Tolerance: 1%
R10 = 10k_0402: RES 12K OHM 1/10W 1% 0603 SMD; Digikey P/N: 311-12.0KHRTR-ND; Manufacturer Part Number: RC0603FR-0712KL; Tolerance: 1%
R19 = 10k_0402: RES 2.2K OHM 1% 1/10W 0603; Digikey P/N: 311-12.0KHRTR-ND; Manufacturer Part Number: RC0603FR-072K2L; Tolerance: 1%
R36 R38 = 0R_0603: RES 150 OHM 1/10W 5% 0603 SMD; Digikey P/N: 541-150GTR-ND; Manufacturer: Vishay; Manufacturer Part Number: CRCW0603150RJNEA
R202 = R: RES 10K OHM 1/10W 5% 0603; COMPFIXED: NO; COMPGROUP: 0; COMPHEIGHT: 0.000; COMPKEY: NO; COMPLOCKED: NO; COMPROT: 180; COMPSIDE: TOP; DECOUPLER: NO; FPLIST: AX/RC05,SM/R_0603; MEMORY: NO; Populate: DI
R262 = R: RES 1K OHM 1/10W 1% 0603 SMD; COMPFIXED: NO; COMPGROUP: 0; COMPHEIGHT: 0.000; COMPKEY: NO; COMPLOCKED: NO; COMPROT: 0; COMPSIDE: TOP; DECOUPLER: NO; FPLIST: AX/RC05; MEMORY: NO; Populate: DI
R263 = R: RES 4.70K OHM 1/10W 1% 0603 SMD; COMPFIXED: NO; COMPGROUP: 0; COMPHEIGHT: 0.000; COMPKEY: NO; COMPLOC: [3325.000,1400.000]; COMPLOCKED: NO; COMPROT: 180; COMPSIDE: TOP; DECOUPLER: NO; FPLIST: AX/RC05; MEMORY: NO; Populate: DI
R264 = R: COMPFIXED: NO; COMPGROUP: 0; COMPHEIGHT: 0.000; COMPKEY: NO; COMPLOCKED: NO; COMPROT: 180; COMPSIDE: BOT; DECOUPLER: NO; MEMORY: NO; Populate: DI
U1 = FT2232HL: IC USB HS DUAL UART/FIFO 64-LQFP
U2 = 93LC56_SO8_0: IC EEPROM 2KBIT 3MHZ 8SOIC
U10 U11 = FSA4157_Analog_Sw
X1 = crystal-3p2x2p5: CRYSTAL 12MHZ 18PF SMD
C15 C16 = 0u1_0402: CAP CER 0.1UF 16V 10% X7R 0402; Assy: DNI
D58 = LED_0603_Red
J14 = Receptacle_20X2_0
R30 R146 R147 R159 R275 R285 R289 = RES_0: Assy: DNI
R31 = RES_0: RES 0.0 OHM 1/10W JUMP 0603 SMD
R33 R34 = 5k1_0402: RES 2.0K OHM 1/10W 5% 0603 SMD; Digikey P/N: 541-2.0KGTR-ND; Manufacturer: Vishay; Manufacturer Part Number: CRCW06032K00JNEA
R35 R37 = 0R_0603: RES 49.9 OHM 1/10W 1% 0603 SMD; Digikey P/N: 541-49.9HTR-ND; Manufacturer: Vishay; Manufacturer Part Number: CRCW060349R9FKEA
R287 = 1k_0402: RES 1K OHM 1/10W 1% 0603 SMD; Digikey P/N: 311-1.00KHRCT-ND; Manufacturer Part Number: RC0603FR-071KL
R288 = RES_0
TP6-TP8 = T_POINT_R
X2 X3 = HDR40_DIP: CONN HEADER VERT 40POS 2.54; ArtNr: 2213; Assembly: Yes; Manufacture: Wurth; ManufactureID: 61304021121; Manufacturer: Wurth; Manufacturer Part Number: 61304021121; Vendor: Technosert

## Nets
5VIN: R30.1 X2.21
+3.3V: C7.1 C10.1 C11.1 C12.1 C13.1 C14.1 C22.1 C26.1 C103.2 C104.2 L1.2 L2.2 R9.2 R11.1 R12.1 R13.1 R152.2 R156.2 R262.1 R264.2 R287.2 U1.20(VCCIO) U1.31(VCCIO) U1.42(VCCIO) U1.50(VREGIN) U1.56(VCCIO) U2.6(ORG) U2.8(VCC) U10.5(VCC) U11.5(VCC) ; also on sheet 8 9 10
+3.3V_AR: J4.4(3V3) ; also on sheet 8 10
+3.3V_RASP: C30.1 JP3.1 JP3.17 ; also on sheet 8 10
+5V_I2C: JP2.4 R78.1
+5V_SPI: JP2.6 R79.1
+12V: C20.1 C24.1 J4.8(VIN) U4.12(PWR_12V) U4.21(PWR_12-0V) U5.12(PWR_12_0V) U5.21(PWR_12V)
GND: C1.2 C2.2 C3.2 C4.2 C5.2 C6.2 C7.2 C8.1 C9.1 C10.2 C11.2 C12.2 C13.2 C14.2 C15.2 C16.2 C17.2 C20.2 C21.2 C22.2 C23.2 C24.2 C25.2 C26.2 C27.2 C28.2 C29.2 C30.2 C97.2 C98.2 C99.2 C100.2 C103.1 C104.1 C116.1 C117.1 C118.1 C119.1 C120.1 C121.1 C122.2 C123.2 C124.2 J1.7 J2.7(GND) J4.6(GND1) J4.7(GND2) J10.2(GND) J10.3(GND) J10.4(GND) J10.5(GND) J14.19 JP2.2 JP2.10 JP3.6 JP3.9 JP3.14 JP3.20 JP3.25 JP3.30 JP3.34 JP3.39 JP4.1 JP9.2 Q42.2(EMITTER) R8.2 R10.1 R48.1 R202.1 R265.2 SW1.5 SW1.6 SW1.7 SW1.8 SW2.2 SW2.3 SW2.4 SW2.5 SW2.6 SW3.2 SW3.3 SW3.4 SW3.5 SW3.6 SW4.2 SW4.3 SW4.4 SW4.5 SW4.6 SW5.2 SW5.3 SW5.4 SW5.5 SW5.6 TP111.1(TP) TP112.1(TP) TP113.1(TP) TP114.1(TP) TP115.1(TP) TP116.1(TP) U1.1(GND) U1.5(GND) U1.10(AGND) U1.11(GND) U1.13(TEST) U1.15(GND) U1.25(GND) U1.35(GND) U1.47(GND) U1.51(GND) U2.5(VSS) U4.3(GND) U4.6(GND) U4.9(GND) U4.15(GND) U4.18(GND) U4.33(GND) U4.34(GND) U4.41(Shield1) U4.42(Shield2) U4.43(Shield3) U4.44(Shield4) U4.45(Shield5) U4.46(Shield6) U5.3(GND) U5.6(GND) U5.9(GND) U5.15(GND) U5.18(GND) U5.33(GND) U5.34(GND) U5.41(Shield1) U5.42(Shield2) U5.43(Shield3) U5.44(Shield4) U5.45(Shield5) U5.46(Shield6) U6.4(GND) U10.2(GND) U11.2(GND) X1.2(G1) X1.4(G2) X2.1 X2.22 X2.24 X2.26 X2.28 X2.30 X2.32 X2.34 X2.36 X2.38 X2.40 X3.2 X3.19 X3.22 X3.24 X3.26 X3.30 X3.34 X3.40 Y2.2(GND) ; also on sheet 8 9 10
VBUS_5V: C21.1 C25.1 JP6.2 JP7.1 R30.2 R78.2 R79.2 R153.2 R155.2 ; also on sheet 8 10
VCC1_8FT: C5.1 C6.1 C23.1 C27.1 C122.1 C123.1 C124.1 R154.2 R157.2 U1.12(VCORE) U1.37(VCORE) U1.49(VREGOUT) U1.64(VCORE) ; also on sheet 8
VCCIO0: J1.1 R1.1 R2.1 R3.1 R31.1 R33.1 R34.1 R146.2 R147.1 R266.1 R267.1 R268.1 R285.1 X2.25 X2.27 ; also on sheet 9 10
VCCIO1: C97.1 R145.2 Y2.4(VDD) ; also on sheet 9 10
VCCIO2: C28.1 R65.1 R66.1 R68.1 R69.1 R80.1 U6.8(VCC) ; also on sheet 9 10
VCCIO5: D20.3(CA3) D20.8(CA8) R39.1 R40.1 R41.1 R42.1 R46.1 R148.1 R149.1 R150.1 ; also on sheet 9 10
12MHZ: JP11.2 U3.B10(PT23A_PCLKT0_1)
ACBUS0: R278.1 U1.26(ACBUS0)
ADBUS0: R4.1 U1.16(ADBUS0)
ADBUS1: R5.1 U1.17(ADBUS1)
ADBUS2: R6.1 U1.18(ADBUS2)
ADBUS3: R7.1 U1.19(ADBUS3)
AR_5V: J4.5(5V0) JP6.1
AR_AD0: J5.1(AD0) U3.P19(PR21C)
AR_AD1: J5.2(AD1) U3.P18(PR21D)
AR_AD2: J5.3(AD2) U3.P17(PR24A)
AR_AD3: J5.4(AD3) U3.P16(PR24B)
AR_AD4: J5.5(AD4/SDA) U3.K22(PR16A)
AR_AD5: J5.6(AD5/SCL) U3.G17(PR7C)
AR_AREF: R43.1 U3.U17(PR29C)
AR_IO0: J3.1(IO0/RXD) U3.G19(PR6C)
AR_IO1: J3.2(IO1/TXD) U3.G20(PR6B)
AR_IO2: J3.3(IO2) U3.G21(PR6A)
AR_IO3: J3.4(IO3/PWM) U3.H20(PR7D)
AR_IO4: J3.5(IO4) U3.G18(PR6D)
AR_IO5: J3.6(IO5/PWM) U3.L21(PR16B)
AR_IO6: J3.7(IO6/PWM) U3.W22(PR25B)
AR_IO7: J3.8(IO7) U3.V22(PR25A)
AR_IO8: J2.1(IO8) U3.U21(PR24D)
AR_IO9: J2.2(IO9/PWM) U3.U22(PR24C)
AR_IO14: J4.1(N/A) U3.T17(PR27C)
AR_MISO_IO12: J2.5(MISO) R77.1 U3.G16(PR2D)
AR_MOSI_IO11: J2.4(MOSI/PWM) R82.2 U3.V18(PR30A)
AR_RESET: J4.3(RESET) U3.U20(PR27D)
AR_SCK_IO13: J2.6(SCK) R76.1 U3.F17(PR2C)
AR_SCL: J2.10(AD5/SCL) R45.1 U3.U18(PR28D)
AR_SDA: J2.9(AD4/SDA) R44.1 U3.U19(PR28C)
AR_SS_IO10: J2.3(SS/PWM) R67.1 U3.W20(PR30B)
ASC_CLK: U3.L1(PL16A_PCLKT4_0) ; also on sheet 8
ASC_RDAT: U3.N1(PL17B) ; also on sheet 8
ASC_RESETb: R275.2 U3.L3(PL16C) ; also on sheet 8
ASC_WDAT: U3.P1(PL18B) ; also on sheet 8
ASC_WRCLK: U3.M1(PL17A) ; also on sheet 8
Bank0_T1: R282.1 R283.2 U3.B21(PT43B)
Bank1_T0: R279.1 R280.2 U3.M22(PR17A_PCLKT1_0)
BDBUS0: R14.1 R23.1 U1.38(BDBUS0)
BDBUS1: R15.1 R24.1 U1.39(BDBUS1)
BDBUS2: R16.1 R25.1 U1.40(BDBUS2)
BDBUS3: R17.1 U1.41(BDBUS3)
BDBUS4: R18.1 U1.43(BDBUS4)
BDBUS5: R20.1 U1.44(BDBUS5)
BDBUS6: R21.1 U1.45(BDBUS6)
BDBUS7: R22.1 U1.46(BDBUS7)
CARDSEL#: R147.2 U3.C13(PT29C) X3.38
CH0_DATA0_N: R53.1 U3.AB4(PB8B) U4.5(CH0_DATA0_N)
CH0_DATA0_P: R53.2 U3.AA4(PB8A) U4.4(CH0_DATA0_P)
CH0_DATA1_N: R57.1 U3.AB2(PB5B) U4.25(CH0_DATA1_N)
CH0_DATA1_P: R57.2 U3.AA2(PB5A) U4.24(CH0_DATA1_P)
CH0_DATA2_N: R61.1 U3.AB5(PB10B) U4.8(CH0_DATA2_N)
CH0_DATA2_P: R61.2 U3.AA5(PB10A) U4.7(CH0_DATA2_P)
CH0_DATA3_N: R50.1 U3.AB8(PB18B) U4.28(CH0_DATA3_N)
CH0_DATA3_P: R50.2 U3.AA8(PB18A) U4.27(CH0_DATA3_P)
CH0_DCK_N: R49.1 U3.AB10(PB22B_PCLKC2_0) U4.2(CH0_DCK_N)
CH0_DCK_P: R49.2 U3.AA10(PB22A_PCLKT2_0) U4.1(CH0_DCK_P)
CH1_DATA0_N: R58.1 U3.AA16(PB38B) U5.5(CH1_DATA0_N)
CH1_DATA0_P: R58.2 U3.AB16(PB38A) U5.4(CH1_DATA0_P)
CH1_DATA1_N: R62.1 U3.AA14(PB33B) U5.25(CH1_DATA1_N)
CH1_DATA1_P: R62.2 U3.AB14(PB33A) U5.24(CH1_DATA1_P)
CH1_DATA2_N: R51.1 U3.AA17(PB40B) U5.8(CH1_DATA2_N)
CH1_DATA2_P: R51.2 U3.AB17(PB40A) U5.7(CH1_DATA2_P)
CH1_DATA3_N: R55.1 U3.AA15(PB35B) U5.28(CH1_DATA3_N)
CH1_DATA3_P: R55.2 U3.AB15(PB35A) U5.27(CH1_DATA3_P)
CH1_DCK_N: R54.1 U3.AA12(PB29B_PCLKC2_1) U5.2(CH1_DCK_N)
CH1_DCK_P: R54.2 U3.AB12(PB29A_PCLKT2_1) U5.1(CH1_DCK_P)
CH2_DATA0_N: R63.1 U3.AB6(PB11B) U4.17(CH2_DATA0_N)
CH2_DATA0_P: R63.2 U3.AA6(PB11A) U4.16(CH2_DATA0_P)
CH2_DATA1_N: R52.1 U3.AB9(PB19B) U4.37(CH2_DATA1_N)
CH2_DATA1_P: R52.2 U3.AA9(PB19A) U4.36(CH2_DATA1_P)
CH2_DCK_N: R59.1 U3.AB7(PB13B) U4.20(CH2_DCK_N)
CH2_DCK_P: R59.2 U3.AA7(PB13A) U4.19(CH2_DCK_P)
CH3_DATA0_N: R60.1 U3.AA18(PB41B) U5.17(CH3_DATA0_N)
CH3_DATA0_P: R60.2 U3.AB18(PB41A) U5.16(CH3_DATA0_P)
CH3_DATA1_N: R64.1 U3.AA20(PB44B) U5.37(CH3_DATA1_N)
CH3_DATA1_P: R64.2 U3.AB20(PB44A) U5.36(CH3_DATA1_P)
CH3_DCK_N: R56.1 U3.AA19(PB43B) U5.20(CH3_DCK_N)
CH3_DCK_P: R56.2 U3.AB19(PB43A) U5.19(CH3_DCK_P)
CS#: JP8.1 R69.2 U6.1(~{CS})
CSSPIN: JP8.2 R86.1 R161.1 R274.2 U3.AA3(PB7A_CSSPIN)
CTSn: R17.2 U3.B14(PT30B)
DCDn: R21.2 U3.A15(PT38A)
DIP_SW1: R39.2 SW1.1 U3.H5(PL11A)
DIP_SW2: R40.2 SW1.2 U3.J5(PL11B)
DIP_SW3: R41.2 SW1.3 U3.J4(PL11C)
DIP_SW4: R42.2 SW1.4 U3.J3(PL11D)
DM: U1.7(DM) ; also on sheet 10
DONE: R268.2 TP8.1(TP) U3.E17(PT44D_DONE)
DP: U1.8(DP) ; also on sheet 10
DSRn: R20.2 U3.B17(PT39B)
DTRn: R18.2 U3.A16(PT39A)
EXPCON_2V5: R146.1 X2.3 X2.23
EXPCON_3V3: R31.2 X2.35 X2.37 X2.39 X3.20
EXPCON_CLKIN: U3.A10(PT23B_PCLKC0_1) X2.31
EXPCON_CLKOUT: U3.A21(PT44A) X2.33
EXPCON_IO0: U3.F8(PT11C) X3.3
EXPCON_IO1: U3.G8(PT11D) X3.4
EXPCON_IO2: U3.F9(PT21C) X3.5
EXPCON_IO3: U3.F7(PT9D) X3.6
EXPCON_IO4: U3.E7(PT13D) X3.7
EXPCON_IO5: U3.E6(PT9C) X3.8
EXPCON_IO6: U3.D5(PT12C) X3.9
EXPCON_IO7: U3.C3(PT10C) X3.10
EXPCON_IO8: U3.D6(PT13C) X3.11
EXPCON_IO9: U3.C4(PT10D) X3.12
EXPCON_IO10: U3.F10(PT22A) X3.13
EXPCON_IO11: U3.C5(PT12D) X3.14
EXPCON_IO12: U3.C6(PT14C) X3.15
EXPCON_IO13: R35.1 U3.B12(PT27C_SCL/PCLKT0_0) X3.16
EXPCON_IO14: U3.D7(PT14D) X3.17
EXPCON_IO15: R37.1 U3.A12(PT27D_SDA/PCLKC0_0) X3.18
EXPCON_IO16: U3.D8(PT15B) X3.21
EXPCON_IO17: U3.C8(PT15A) X3.23
EXPCON_IO18: U3.D9(PT20D) X3.25
EXPCON_IO19: U3.E10(PT22B) X3.27
EXPCON_IO20: R275.1 U3.C9(PT20C) X3.28
EXPCON_IO21: U3.G11(PT23C) X3.29
EXPCON_IO22: U3.E11(PT24C) X3.31
EXPCON_IO23: U3.D11(PT24D) X3.32
EXPCON_IO24: U3.F11(PT23D) X3.33
EXPCON_IO25: U3.D12(PT27A) X3.35
EXPCON_IO26: U3.F12(PT28B) X3.36
EXPCON_IO27: U3.D13(PT29D) X3.37
EXPCON_IO28: U3.C14(PT30C) X3.39
EXPCON_IO29: U3.E12(PT27B) X2.4
EXPCON_IO30: U3.D14(PT30D) X2.5
EXPCON_IO31: U3.C15(PT38C) X2.6
EXPCON_IO32: U3.C17(PT39C) X2.7
EXPCON_IO33: U3.D15(PT38D) X2.8
EXPCON_IO34: U3.C18(PT41C) X2.9
EXPCON_IO35: U3.D16(PT39D) X2.10
EXPCON_IO36: U3.C19(PT43C) X2.11
EXPCON_IO37: U3.D17(PT40D) X2.12
EXPCON_IO38: U3.D18(PT41D) X2.13
EXPCON_IO39: U3.C20(PT43D) X2.14
EXPCON_IO40: U3.E16(PT40C) X2.15
EXPCON_IO41: U3.E13(PT28C) X2.16
EXPCON_IO42: U3.F13(PT28D) X2.17
EXPCON_IO43: U3.F15(PT42C) X2.18
EXPCON_IO44: U3.G15(PT42D) X2.19
EXPCON_IO45: U3.G12(PT28A) X2.20
EXPCON_OSC: R159.1 X2.29
EXT_CLK: J10.1(CENTER) R144.2
FT_EECLK: R12.2 U1.62(EECLK) U2.2(CLK)
FT_EECS: R11.2 U1.63(EECS) U2.1(CS)
FT_EEDATA: R19.1 U1.61(EEDATA) U2.3(DI)
FT_OSCI: C8.2 U1.2(OSCI) X1.1
FT_OSCO: C9.2 JP11.1 U1.3(OSCO) X1.3
FT_REF: R10.2 U1.6(REF)
FT_RSTb: JP9.1 R9.1 U1.14(RESET#)
FT_VPHY: C3.1 C4.1 L2.1 U1.4(VPHY)
FT_VPLL: C1.1 C2.1 L1.1 U1.9(VPLL)
FTDI_SCL: R23.2 TP1.1(TP) U10.1(B1_NO)
FTDI_SDA: R24.2 R25.2 TP2.1(TP) U11.1(B1_NO)
FX_MISO: R273.1 U4.31(MISO) U5.31(MISO)
FX_MOSI: R272.1 U4.30(MOSI) U5.30(MOSI)
FX_SCLK: R271.1 U4.11(SCLK) U5.11(SCLK)
FX_SN: R274.1 U4.10(SN) U5.10(SN)
GDDR_DQ0: TP93.1(TP) U3.R22(PR20A)
GDDR_DQ1: TP94.1(TP) U3.R21(PR20B)
GDDR_DQ2: TP95.1(TP) U3.T22(PR21A)
GDDR_DQ3: TP96.1(TP) U3.T21(PR21B)
GDDR_DQ4: TP97.1(TP) U3.Y22(PR28A)
GDDR_DQ5: TP98.1(TP) U3.W21(PR28B)
GDDR_DQ6: TP99.1(TP) U3.AA22(PR29A)
GDDR_DQ7: TP100.1(TP) U3.Y21(PR29B)
GDDR_DQS: TP101.1(TP) U3.N22(PR19A)
GDDR_DQSN: TP102.1(TP) U3.P21(PR19B)
HOLD#: R65.2 U3.W8(PB16D) U6.7(~{HOLD})
HPE_RESOUT#: U3.G9(PT21D) X3.1
I2C_EN_LED_DR: Q42.1(BASE) R263.1
I2C_SCL0: R98.2 U3.K1(PL14B) ; also on sheet 8
I2C_SDA0: R97.2 U3.K2(PL14A) ; also on sheet 8
I2C_WRITE_PROTECT: U3.N2(PL18A) ; also on sheet 8
I3C_AA1: TP3.1(TP) U3.AA1(PL29B)
I3C_T2: TP9.1(TP) U3.T2(PL25A)
I3C_U1: TP5.1(TP) U3.U1(PL25B)
I3C_Y1: TP4.1(TP) U3.Y1(PL29A)
INITN: R267.2 TP7.1(TP) U3.F16(PT44C_INITN)
JP2_SCL: JP2.1 U10.3(B0_NC)
JP2_SDA: JP2.3 U11.3(B0_NC)
JTAGENB: R265.1 TP6.1(TP) U3.E14(PT31C_JTAGENB)
LED_24mA: D58.2(CATHODE) R288.1 R289.1
LED_A19: R288.2 U3.A19(PT42A)
LED_B20: R289.2 U3.B20(PT42B)
LVDS_OUT0_N: J14.2 U3.A2(PT9B)
LVDS_OUT0_P: J14.1 U3.B1(PT9A)
LVDS_OUT1_N: J14.4 U3.A3(PT10B)
LVDS_OUT1_P: J14.3 U3.B2(PT10A)
LVDS_OUT3_N: J14.8 U3.A5(PT12B)
LVDS_OUT3_P: J14.7 U3.B4(PT12A)
LVDS_OUT4_N: J14.10 U3.A6(PT13B)
LVDS_OUT4_P: J14.9 U3.B5(PT13A)
LVDS_OUT5_N: J14.12 U3.A7(PT14B)
LVDS_OUT5_P: J14.11 U3.B6(PT14A)
LVDS_OUT6_N: J14.13 U3.A8(PT20B)
LVDS_OUT6_P: J14.14 U3.B8(PT20A)
LVDS_OUT7_N: J14.15 U3.A9(PT21B)
LVDS_OUT7_P: J14.16 U3.B9(PT21A)
LVDS_OUT8_N: J14.18 U3.A11(PT24B)
LVDS_OUT8_P: J14.17 U3.B11(PT24A)
MCLK: JP2.7 R74.1 R76.2 R89.1 R271.2 U3.T9(PB16A_MCLK/CCLK)
OSC_EN: JP4.2 R145.1 U3.L20(PR14D) Y2.1(Standby)
OSC_IN: R144.1 R159.2 U3.D22(PR3A_R_GPLLT_IN) Y2.3(OUT)
PB1: C17.1 R46.2 SW2.1 TP89.1(TP) U3.D3(PL2A)
PB2: C98.1 R148.2 SW3.1 TP90.1(TP) U3.D4(PL2B)
PB3: C99.1 R149.2 SW4.1 TP91.1(TP) U3.F6(PL2C)
PB4: C100.1 JP5.2 R150.2 SW5.1 U3.G7(PL2D)
PROGRAMN: JP5.1 R266.2 U3.E15(PT31D_PROGRAMN)
PWR_1-8V_L: R154.1 U4.29(PWR_1-8V) U4.32(PWR_1-8V)
PWR_1-8V_R: R157.1 U5.29(PWR_1-8V) U5.32(PWR_1-8V)
PWR_3-3V_L: R152.1 U4.26(PWR_3-3V) U4.35(PWR_3-3V)
PWR_3-3V_R: R156.1 U5.26(PWR_3-3V) U5.35(PWR_3-3V)
PWR_5-0V_L: R153.1 U4.23(PWR_5-0V) U4.38(PWR_5-0V)
PWR_5-0V_R: R155.1 U5.23(PWR_5-0V) U5.38(PWR_5-0V)
RASP_5V: C29.1 JP3.2 JP3.4 JP7.2
RASP_ID_SC: JP3.28 R85.1 U3.T7(PL30D)
RASP_ID_SD: JP3.27 R87.1 U3.V5(PL30C)
RASP_IO02: JP3.3 R292.2 U3.U2(PL27A_PCLKT3_0)
RASP_IO03: JP3.5 R96.1 U3.V1(PL27B_PCLKC3_0)
RASP_IO04: JP3.7 U3.T6(PL26D)
RASP_IO05: JP3.29 U3.U3(PL27C)
RASP_IO06: JP3.31 U3.U4(PL27D)
RASP_IO07: JP3.26 R86.2 U3.T5(PL26C)
RASP_IO08: JP3.24 R88.2 U3.T4(PL26B)
RASP_IO09: JP3.21 R92.2 U3.R7(PL25D)
RASP_IO10: JP3.19 R94.2 U3.R6(PL25C)
RASP_IO11: JP3.23 R89.2 U3.T3(PL26A)
RASP_IO12: JP3.32 U3.V4(PL28C)
RASP_IO13: JP3.33 U3.U5(PL28D)
RASP_IO14: JP3.8 R95.2 U3.P4(PL20A)
RASP_IO15: JP3.10 R90.2 U3.N5(PL20B)
RASP_IO16: JP3.36 U3.W4(PL30B)
RASP_IO17: JP3.11 R93.2 U3.N6(PL20C)
RASP_IO18: JP3.12 R91.2 U3.N7(PL20D)
RASP_IO19: JP3.35 U3.W3(PL29C)
RASP_IO20: JP3.38 U3.Y2(PL29D)
RASP_IO21: JP3.40 U3.Y3(PL30A)
RASP_IO22: JP3.15 U3.P6(PL21D)
RASP_IO23: JP3.16 U3.R3(PL24A)
RASP_IO24: JP3.18 U3.R4(PL24B)
RASP_IO25: JP3.22 U3.R5(PL24C)
RASP_IO26: JP3.37 U3.P7(PL24D)
RASP_IO27: JP3.13 U3.P5(PL21C)
RESETN: U3.AB3(PB7B) U4.22(RESETN) U5.22(RESETN)
RI: R22.2 U3.B15(PT38B)
RS232_Rx_TTL: R14.2 U3.A13(PT29A)
RS232_Tx_TTL: R15.2 U3.B13(PT29B)
RTSn: R16.2 U3.A14(PT30A)
SCK: R48.2 R68.2 R74.2 U6.6(SCK)
SCL0: C15.1 R33.2 R35.2 R36.1 R45.2 R70.2 R83.1 R85.2 R96.2 R98.1
SCL1: R83.2 U3.AB11(PB24B) U4.40(SCL) U5.40(SCL)
SCL2: R70.1 U3.AA13(PB30B) U4.14(SCL1) U5.14(SCL1)
SDA0: C16.1 R34.2 R37.2 R38.1 R44.2 R71.2 R81.1 R87.2 R97.1 R292.1
SDA1: R81.2 U3.AA11(PB24A) U4.39(SDA) U5.39(SDA)
SDA2: R71.1 U3.AB13(PB30A) U4.13(SDA1) U5.13(SDA1)
SDI: R72.2 U6.5(SDI)
SDO: R73.1 U6.2(SDO)
SEG_A: R183.2 U3.G2(PL7A_PCLKT5_0)
SEG_B: R184.2 U3.D1(PL5A)
SEG_C: R185.2 U3.C1(PL4A_L_GPLLT_IN)
SEG_D: R186.2 U3.D2(PL4B_L_GPLLC_IN)
SEG_DP: R190.2 U3.F1(PL6B)
SEG_E: R187.2 U3.E2(PL5B)
SEG_F: R188.2 U3.E3(PL5C)
SEG_G: R189.2 U3.E1(PL6A)
SISPI: JP2.8 R72.1 R82.1 R94.1 R272.2 U3.AA21(PB46B_SI/SISPI)
SN: R80.2 R88.1 R160.2 U3.AB21(PB46A_SN)
SPISO: JP2.5 R73.2 R77.2 R92.1 R273.2 U3.U9(PB16B_SO/SPISO)
SS: JP2.9 R67.2 R160.1 R161.2
TCK: J1.8 R4.2 R8.1 R95.1 U3.D10(PT22C_TCK)
TDI: J1.3 R2.2 R5.2 R93.1 U3.E9(PT15D_TDI)
TDO: J1.2 R3.2 R6.2 R90.1 U3.E8(PT15C_TDO)
TMS: J1.6 R1.2 R7.2 R91.1 U3.C10(PT22D_TMS)
USB_I2C_EN: JP10.1 R202.2 R263.2 R278.2 U10.6(S_CTRL) U11.6(S_CTRL)
VREF_BANK0: U3.A18(PT41A) ; also on sheet 8
WP#: R66.2 U3.V9(PB16C) U6.3(~{WP})
XLED0: U3.G1(PL7B_PCLKC5_0) ; also on sheet 9
XLED1: U3.H2(PL10A) ; also on sheet 9
XLED2: U3.J2(PL12A) ; also on sheet 9
XLED3: U3.F4(PL5D) ; also on sheet 9
XLED4: U3.H1(PL10B) ; also on sheet 9
XLED5: U3.J1(PL12B) ; also on sheet 9
XLED6: U3.G3(PL6C) ; also on sheet 9
XLED7: U3.G4(PL6D) ; also on sheet 9
N16794205: R13.2 R19.2 U2.4(DO)
N17088645: R36.2 U10.4(A_IN)
N17088667: R38.2 U11.4(A_IN)
N17088710: JP10.2 R262.2
N17128437: D57.1(ANODE) R264.1
N17137399: J2.8(AREF) R43.2
N17338066: D58.1(ANODE) R287.1
N17339229: D20.5(DP) R190.1
N17339257: D20.10(G) R189.1
N17339273: D20.9(F) R188.1
N17339290: D20.1(E) R187.1
N17339303: D20.2(D) R186.1
N17339318: D20.4(C) R185.1
N17339331: D20.6(B) R184.1
N17339344: D20.7(A) R183.1
N17345119: C116.2 R279.2 TP105.1(TP)
N17345123: R280.1 R281.2 R290.1
N17345165: C118.2 R290.2 TP107.1(TP)
N17345169: C120.2 R281.1 TP109.1(TP)
N17345268: C117.2 R282.2 TP106.1(TP)
N17345272: R283.1 R284.2 R291.1
N17345314: C119.2 R291.2 TP108.1(TP)
N17345318: C121.2 R284.1 TP110.1(TP)
N17360829: J14.20 R285.2
N17429878: D57.2(CATHODE) Q42.3(COLLECTOR)

Not connected (* = marked no-connect by the designer): J1 4* 5*; J4 2(IOREF)*; J14 5* 6*; U1 21(ADBUS4)* 22(ADBUS5)* 23(ADBUS6)* 24(ADBUS7)* 27(ACBUS1)* 28(ACBUS2)* 29(ACBUS3)* 30(ACBUS4)* 32(ACBUS5)* 33(ACBUS6)* 34(ACBUS7)* 36(SUSPEND#)* 48(BCBUS0)* 52(BCBUS1)* 53(BCBUS2)* 54(BCBUS3)* 55(BCBUS4)* 57(BCBUS5)* 58(BCBUS6)* 59(BCBUS7)* 60(PWREN#)*; U2 7(NU)*; U3 A4(PT11B)* A17(PT40A)* B18(PT40B)* B19(PT41B)* B22(PT44B)* C21(PR2A_R_GPLLT_FB) C22(PR2B_R_GPLLC_FB) D19(PR3C)* D20(PR3D)* D21(PR3B_R_GPLLC_IN) E4(PL3A_L_GPLLT_FB)* E19(PR4C)* E20(PR4D)* E21(PR4B)* E22(PR4A)* F5(PL3B_L_GPLLC_FB)* F14(PT31B)* F18(PR5C)* F19(PR5D)* F22(PR5A)* G5(PL4C)* G6(PL3C)* G14(PT31A)* G22(PR5B)* H3(PL7D)* H4(PL7C)* H6(PL4D)* H7(PL3D)* H16(PR10D)* H17(PR10C)* H18(PR10B)* H19(PR10A)* H21(PR7B)* H22(PR7A)* J6(PL10D)* J7(PL10C)* J16(PR11A)* J17(PR11B)* J18(PR11C)* J19(PR11D)* J20(PR12C)* J21(PR12A)* J22(PR12B)* K3(PL13D)* K4(PL13C)* K5(PL13B)* K6(PL12D)* K7(PL12C)* K16(PR13D)* K17(PR13C)* K18(PR13B)* K19(PR13A)* K20(PR12D)* L4(PL16D)* L5(PL14D)* L6(PL14C)* L7(PL13A)* L16(PR14B)* L17(PR14A)* L19(PR14C)* L22(PR16C)* M2(PL16B_PCLKC4_0)* M5(PL17D)* M6(PL17C)* M7(PL19D)* M16(PR18A)* M17(PR16D)* M19(PR17D)* M20(PR17C)* M21(PR17B_PCLKC1_0) N3(PL18C)* N4(PL18D)* N16(PR18B)* N17(PR18C)* N18(PR18D)* N19(PR19D)* N20(PR19C)* P2(PL19A)* P3(PL19C)* P20(PR20D)* P22(PR20C)* R1(PL19B)* R2(PL21A)* R16(PR26C)* R17(PR26B)* R18(PR26A)* R19(PR25D)* R20(PR25C)* T1(PL21B)* T8(PB8D)* T10(PB19C)* T11(PB22C)* T12(PB27B)* T13(PB32A)* T14(PB32B)* T15(PB43C)* T16(PB46D)* T18(PR27B)* T19(PR27A)* T20(PR26D)* U6(PB5D)* U7(PB8C)* U8(PB13D)* U10(PB19D)* U11(PB22D)* U12(PB27C)* U13(PB29D)* U14(PB32C)* U15(PB38D)* U16(PB43D)* V6(PB5C)* V7(PB11D)* V8(PB13C)* V10(PB21A)* V11(PB24C)* V12(PB27D)* V13(PB29C)* V14(PB32D)* V15(PB38C)* V16(PB40D)* V17(PB46C)* V19(PR29D)* W1(PL28A)* W2(PL28B)* W5(PB7D)* W6(PB11C)* W9(PB18D)* W10(PB21B)* W13(PB30D)* W14(PB33D)* W15(PB35D)* W17(PB41D)* W18(PB44D)* W19(PR30C)* Y4(PB7C)* Y5(PB10C)* Y6(PB10D)* Y8(PB18C)* Y9(PB21C)* Y10(PB21D)* Y11(PB24D)* Y12(PB27A)* Y13(PB30C)* Y14(PB33C)* Y15(PB35C)* Y17(PB40C)* Y18(PB41C)* Y19(PB44C)* Y20(PR30D)*; X2 2*

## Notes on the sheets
sheet 1
- MachXO4 Development Board
- Rev - A
- 01 - Title page
  02 - Block diagram
  03 - USB to JTAG I/F
  04 - Versa connector (BANK0)
  05 - Arduino Header (BANK1)
  06 - CrossLink Header (BANK2)
  07 - Raspberry Pi (BANK3&4&5)
  08 - Analog Sense and Control
  09 - POWER DECOUPLING AND LED'S
  10 - POWER REGULATORS
sheet 3
- FOR FUTURE RS232 FUNCTION
- B1 connected to A when S_CTRL is high
sheet 4
- VERSA Connectors
- Pin 2 removed for coding
  of expansion board
- LVDS OUTPUT layout equal length
  (Swap P and N of LVDS OUT 6/7 for easy layout)
- DNI
- HS LVDS OUT TEST POINTS
sheet 5
- ARDUINO Connector
- 4 inch trace
- 4 inch trace
- 8 inch trace
- 4 inch trace
- 4 inch trace
- 8 inch trace
- 50ohm trace
- 2.5 x 2.0 mm 4-SMD
- PLACE Y2 CLOSE TO U3
- TEST PADs close to U3
sheet 6
- CrossLink Headers
- NOTE : PLACE ALL THE TERMINATION
  RESISTORS ON TOP SIDE AND CLOSE
  TO THE U3
- LVDS RX TERMINATION RESISTORS
- RX Connector2
- RX Connector1
- Note :
  1) Match length within pair as well as other pairs with +/- 5% tolerence
  2)Differential impedance should be 100 Ohms and 50 Ohms as a single ended signals
  3)All the power rails should be capable of carrying 1A current
- Note : Speed of the bus, < 2.5ps skew for pairs and
  across the bus, traces should be 100 Ohms
  Trace match LVDSI* pins between P and N channels as
  well as individual pairs.
- SPI FLASH
- NOTE : 0 OHM RESISTOR SHUOULD BE PLACED
  NEAR U3
- SPI FLASH
- AARDVARK
  Connector
- NOTE : 0 OHM RESISTOR SHUOULD BE PLACED
  NEAR U3
- AARDVARK
sheet 7
- Character Signal Map
- U3 pin
- D18 pin
- Segment
- E4
- 5
- DP
- F5
- 10
- G
- G6
- 9
- F
- H7
- 1
- E
- C1
- 2
- D
- D2
- 4
- C
- G5
- 6
- B
- H6
- 7
- A
- 7-SEGMENT DISPLAY
- Raspberry PI Connector
- NOTE : PLACE SWITCH ON THE TOP SIDE
